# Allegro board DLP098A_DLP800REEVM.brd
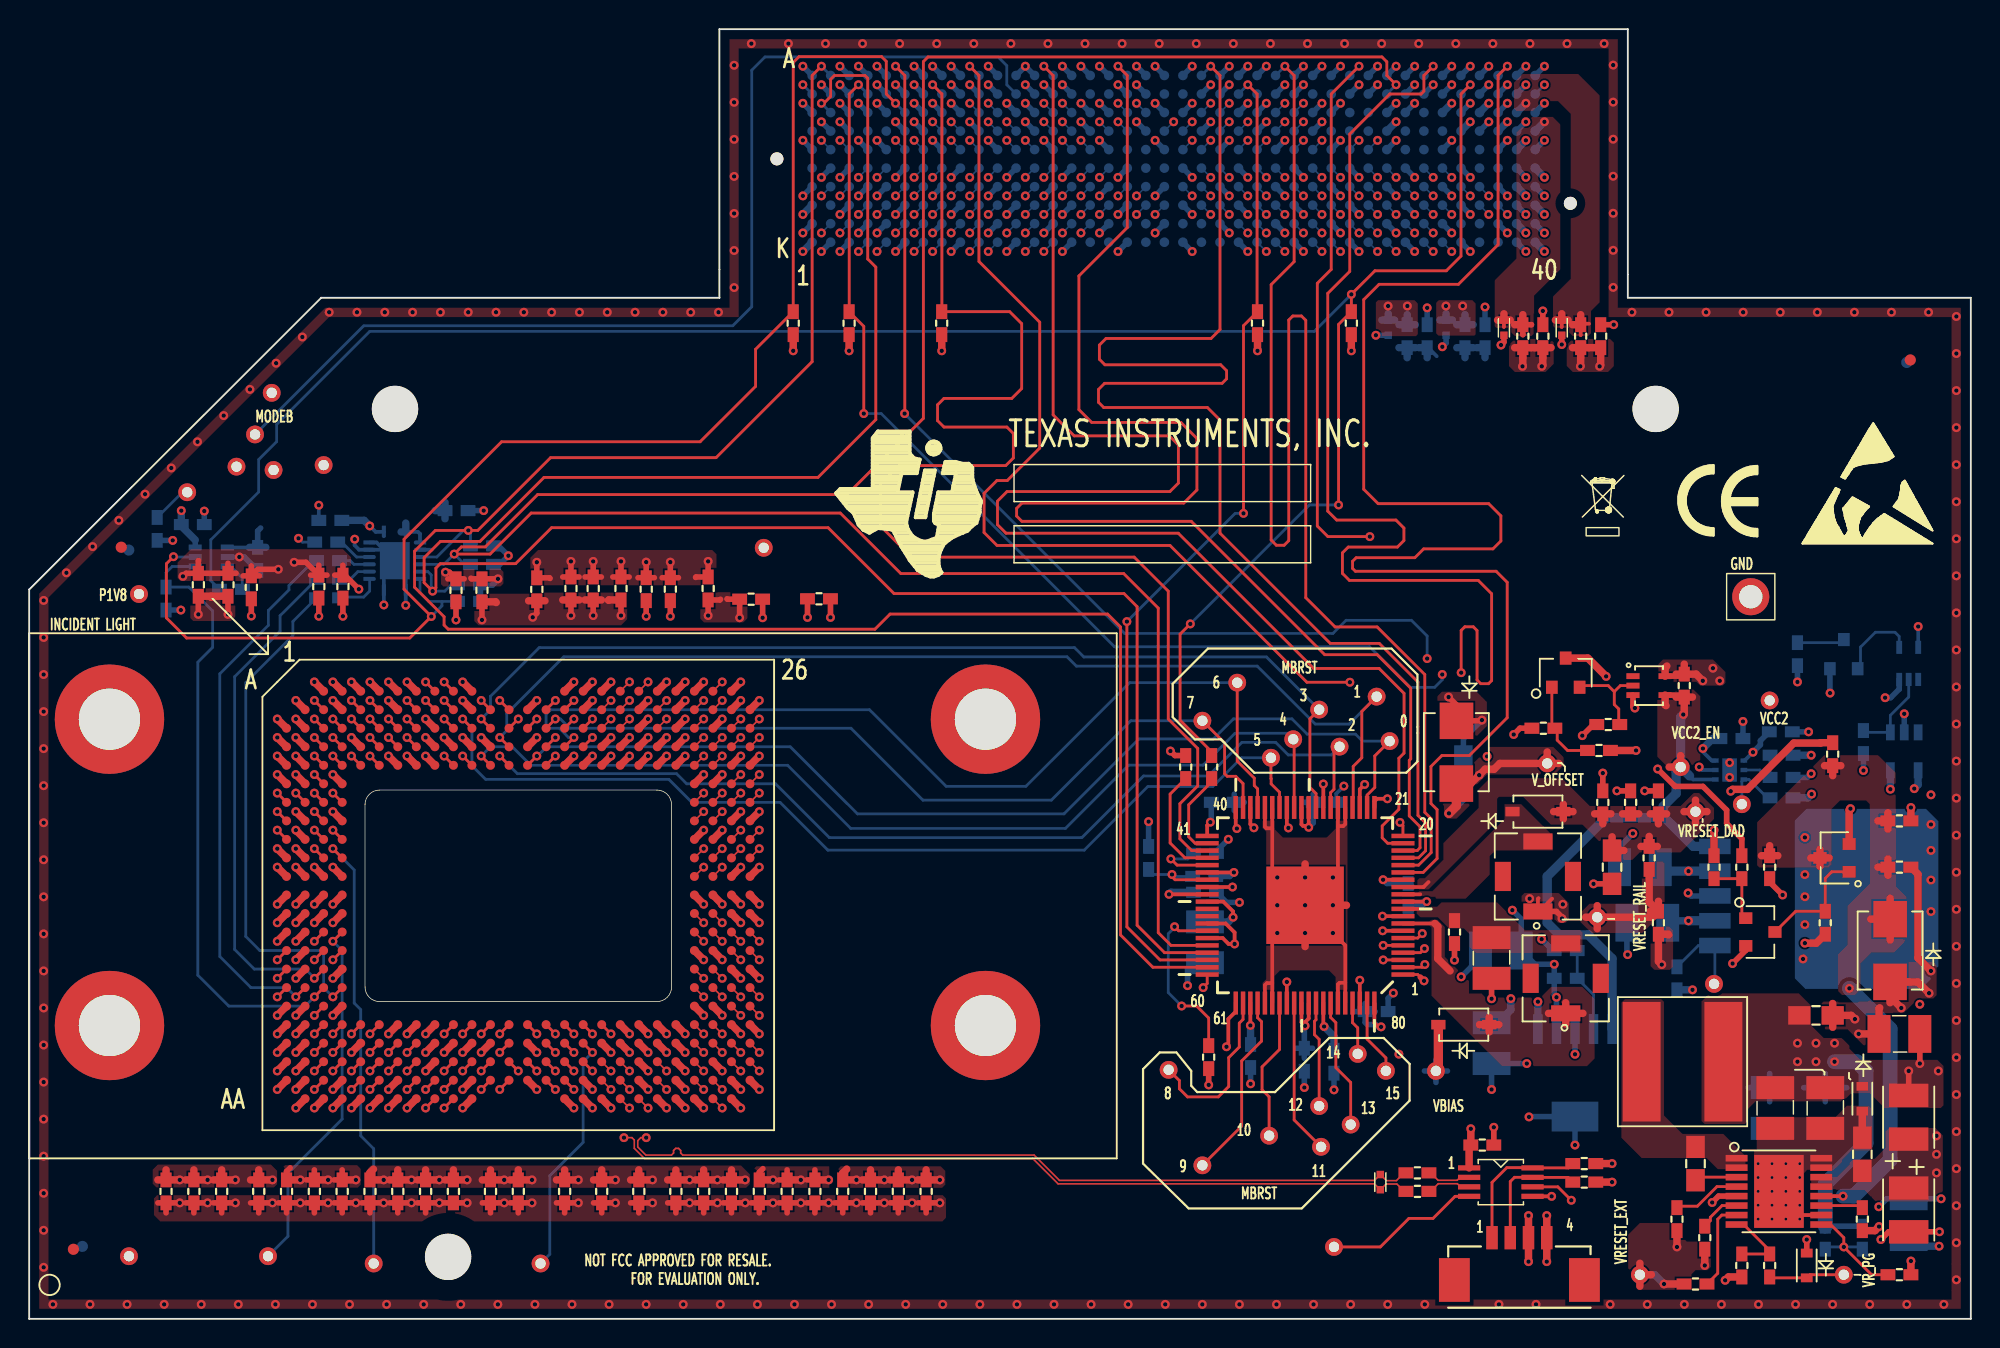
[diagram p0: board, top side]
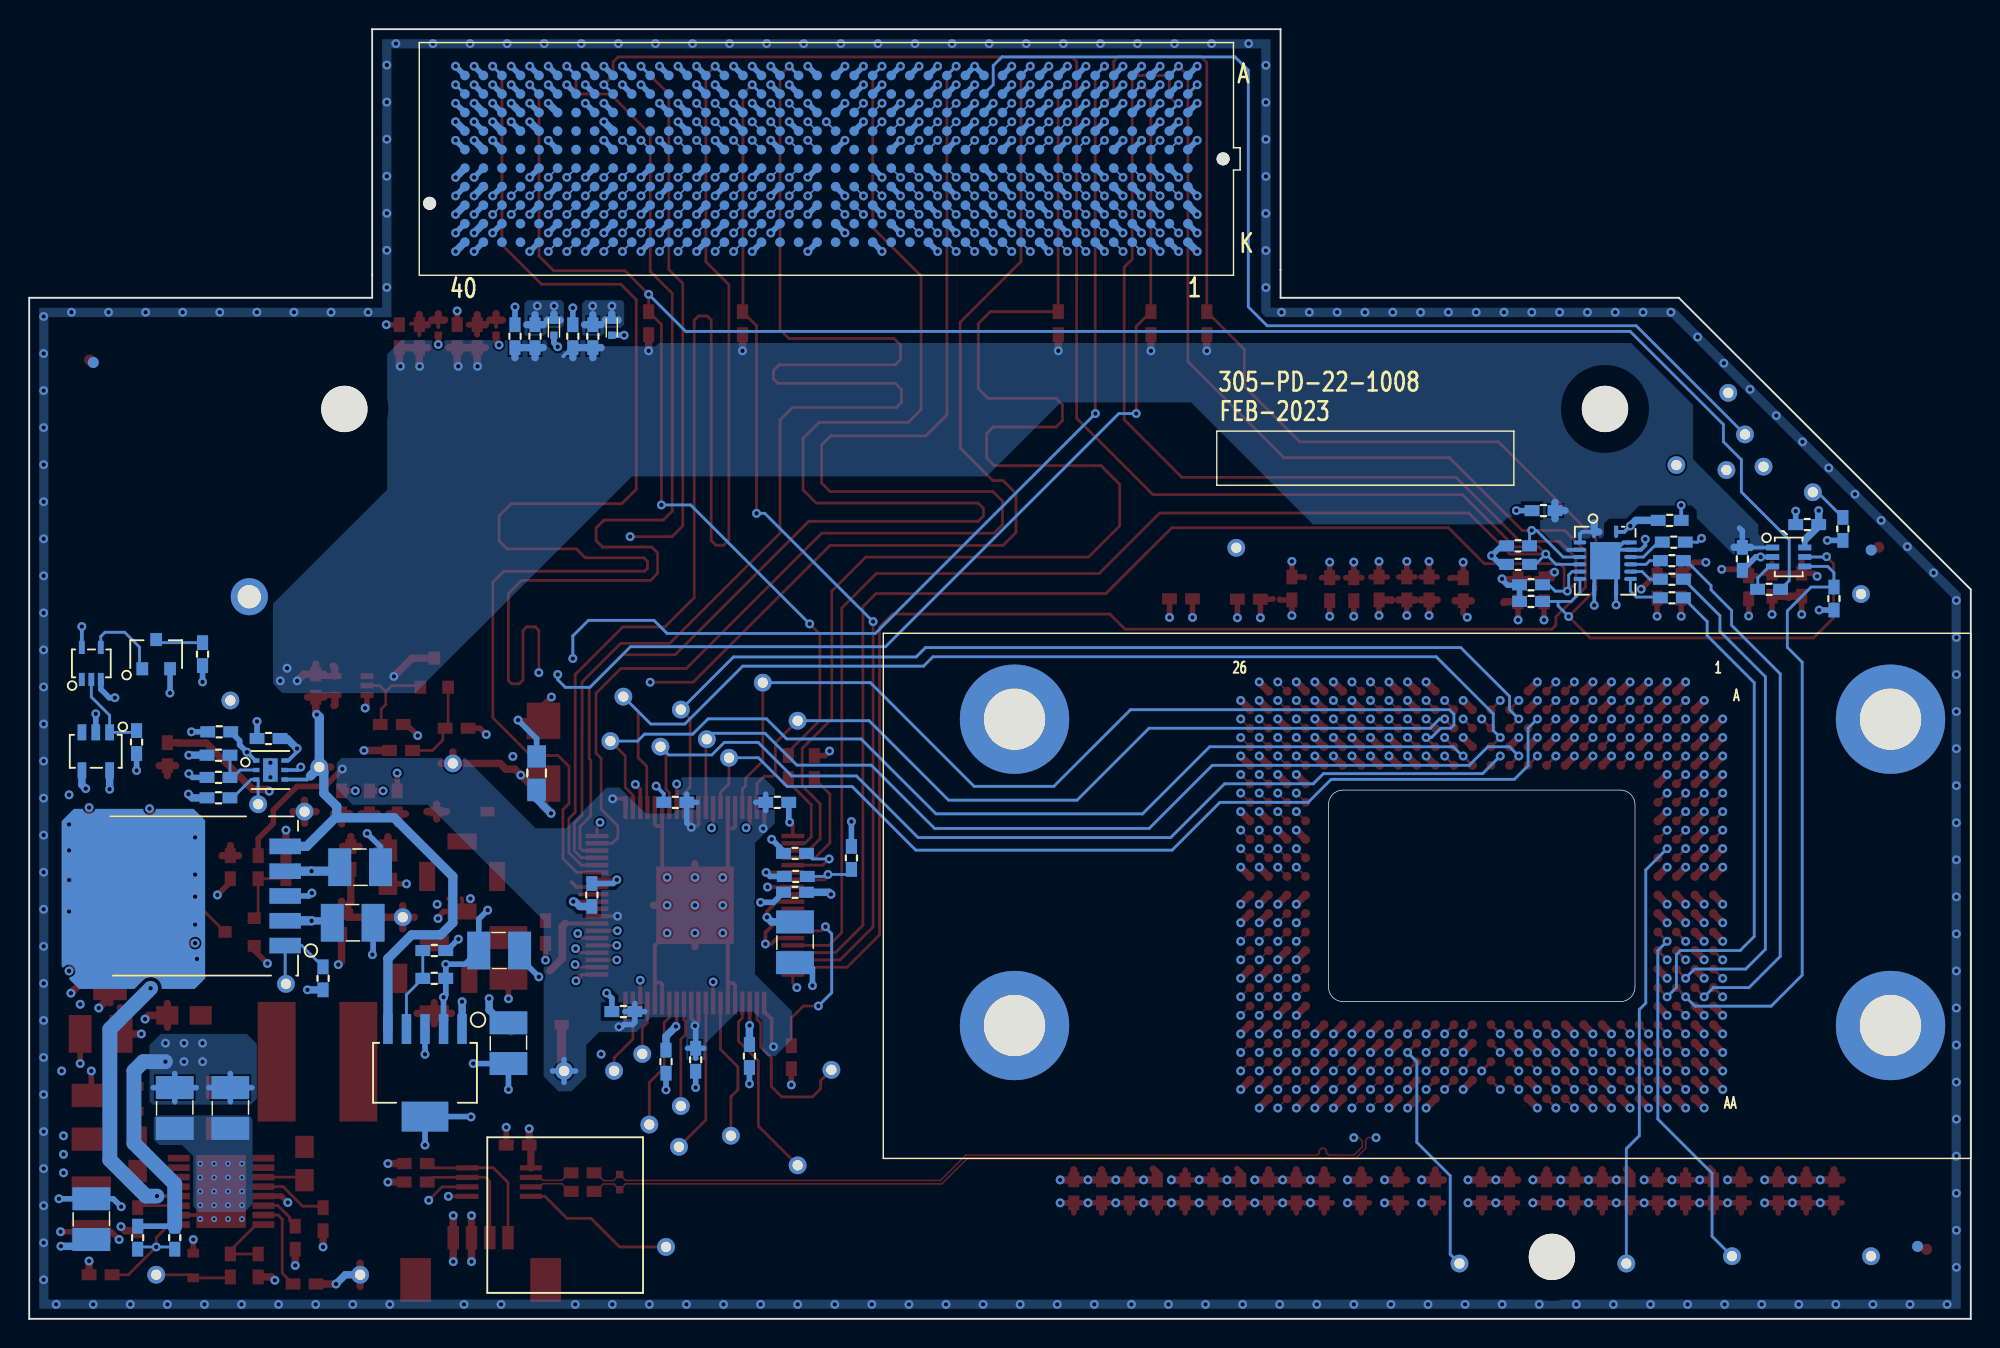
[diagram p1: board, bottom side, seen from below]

Outline 133.01 x 88.41 mm; copper layers: TOP, 02_GND1, 03_SIG1, 04_GND2, 05_SIG2, 06_PWR1, 07_PWR2, 08_SIG3, 09_GND3, 10_SIG4, 11_GND4, BOTTOM. Coordinates in mm from the lower left corner of the outline.
Outline path: 0,50 0,0 133.01,0 133.01,70 109.51,70 109.51,88.41 47.28,88.41 47.28,70 20,70 0,50 ; 23,35.25 23,22.75 arc(23.3,22.04) 24,21.75 43,21.75 arc(43.71,22.04) 44,22.75 44,35.25 arc(43.71,35.96) 43,36.25 24,36.25 arc(23.3,35.96) 23,35.25

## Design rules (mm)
net group DIFFPAIR36: nets DMD_TEMP_N DMD_TEMP_P
net group DIFFPAIR37: nets N16883881 N16883884
net group DIFF-A: nets S_DCLKA_N S_DCLKA_P S_DDA00_N S_DDA00_P S_DDA01_N S_DDA01_P S_DDA02_N S_DDA02_P S_DDA03_N S_DDA03_P S_DDA04_N S_DDA04_P S_DDA05_N S_DDA05_P S_DDA06_N S_DDA06_P S_DDA07_N S_DDA07_P S_DDA08_N S_DDA08_P S_DDA09_N S_DDA09_P S_DDA10_N S_DDA10_P S_DDA11_N S_DDA11_P S_DDA12_N S_DDA12_P S_DDA13_N S_DDA13_P S_DDA14_N S_DDA14_P S_DDA15_N S_DDA15_P S_SCTRLA_N S_SCTRLA_P
net group DIFF-B: nets S_DCLKB_N S_DCLKB_P S_DDB00_N S_DDB00_P S_DDB01_N S_DDB01_P S_DDB02_N S_DDB02_P S_DDB03_N S_DDB03_P S_DDB04_N S_DDB04_P S_DDB05_N S_DDB05_P S_DDB06_N S_DDB06_P S_DDB07_N S_DDB07_P S_DDB08_N S_DDB08_P S_DDB09_N S_DDB09_P S_DDB10_N S_DDB10_P S_DDB11_N S_DDB11_P S_DDB12_N S_DDB12_P S_DDB13_N S_DDB13_P S_DDB14_N S_DDB14_P S_DDB15_N S_DDB15_P S_SCTRLB_N S_SCTRLB_P
net group DIFF-C: nets M_DCLKA_N M_DCLKA_P M_DDA00_N M_DDA00_P M_DDA01_N M_DDA01_P M_DDA02_N M_DDA02_P M_DDA03_N M_DDA03_P M_DDA04_N M_DDA04_P M_DDA05_N M_DDA05_P M_DDA06_N M_DDA06_P M_DDA07_N M_DDA07_P M_DDA08_N M_DDA08_P M_DDA09_N M_DDA09_P M_DDA10_N M_DDA10_P M_DDA11_N M_DDA11_P M_DDA12_N M_DDA12_P M_DDA13_N M_DDA13_P M_DDA14_N M_DDA14_P M_DDA15_N M_DDA15_P M_SCTRLA_N M_SCTRLA_P
net group DIFF-D: nets M_DCLKB_N M_DCLKB_P M_DDB00_N M_DDB00_P M_DDB01_N M_DDB01_P M_DDB02_N M_DDB02_P M_DDB03_N M_DDB03_P M_DDB04_N M_DDB04_P M_DDB05_N M_DDB05_P M_DDB06_N M_DDB06_P M_DDB07_N M_DDB07_P M_DDB08_N M_DDB08_P M_DDB09_N M_DDB09_P M_DDB10_N M_DDB10_P M_DDB11_N M_DDB11_P M_DDB12_N M_DDB12_P M_DDB13_N M_DDB13_P M_DDB14_N M_DDB14_P M_DDB15_N M_DDB15_P M_SCTRLB_N M_SCTRLB_P
net group MBRST: nets MBRST0 MBRST1 MBRST2 MBRST3 MBRST4 MBRST5 MBRST6 MBRST7 MBRST8 MBRST9 MBRST10 MBRST11 MBRST12 MBRST13 MBRST14 MBRST15
net group PLN: nets N16949505
net group PWR: nets 3P3VAUX P3P3V1 P3P3V2 P3P3V3 P3P3V4 VADJ VIO_B_M2C VREF_A_M2C VREF_B_M2C VRESET_EN
net group SCP: nets SCP_CLK SCP_DMD_CSZ SCP_MISO SCP_MOSI
nets with their own width: min track width 0.381; nets GND VBIAS VCC2
nets with their own width: min track width 0.508; nets P12V

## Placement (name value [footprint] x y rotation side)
ASY1  -  []  96.34 7.16 180 bottom
C1  0.1 uF  [0603]  107.66 67.37 270 top
C2  1000 pF  [0402]  104.99 67.95 90 top
C3  1000 pF  [0402]  97.06 67.95 90 bottom
C4  0.1 uF  [0603]  99.73 67.37 270 bottom
C5  0.1 uF  [0603]  95.77 67.37 270 bottom
C6  1000 pF  [0402]  93.1 67.95 90 bottom
C7  1000 pF  [0402]  101.03 67.95 90 top
C8  0.1 uF  [0603]  103.69 67.37 270 top
C9  1 uF  [0603]  116.61 39.78 180 bottom
C10  10 uF  [1210]  110.34 30.96 0 bottom
C11  2.2 uF  [0603]  119.99 40.24 180 bottom
C12  10 uF  [1210]  110.85 27.15 0 bottom
C13  0.1 uF  [0603]  83.67 18.02 90 bottom
C14  0.1 uF  [0603]  89.38 17.63 90 bottom
C15  0.1 uF  [0603]  80.55 29.24 180 bottom
C16  4.7 uF  [0805]  98.25 37.41 270 bottom
C17  0.1 uF  [0603]  94.46 29.06 270 bottom
C18  10 uF  [1210]  80.55 25.81 90 bottom
C19  1 uF  [0603]  80.49 30.33 180 bottom
C20  0.1 uF  [0603]  76.68 31.6 270 bottom
C21  0.1 uF  [0603]  107.8 35.41 270 top
C22  0.1 uF  [0603]  109.7 35.41 270 top
C23  0.1 uF  [0603]  111.61 35.41 270 top
C24  4.7 uF  [0805]  108.43 30.96 90 top
C25  0.1 uF  [0603]  87.35 17.76 90 bottom
C26  0.1 uF  [0603]  92.31 21.06 180 bottom
C27  1 uF  [0603]  81.76 35.41 0 bottom
C28  1 uF  [0603]  88.75 35.41 180 bottom
C29  10 uF  [1210]  100.18 24.74 90 top
C30  0.1 uF  [0603]  97.64 26.52 90 top
C31  1 uF  [0603]  17.63 8.74 90 top
C32  1 uF  [0603]  19.53 8.74 90 top
C33  1 uF  [0603]  50.01 8.74 90 top
C34  1 uF  [0603]  53.82 8.74 90 top
C35  1 uF  [0603]  42.27 50.02 270 top
C36  1 uF  [0603]  21.49 50.2 270 top
C37  0.1 uF  [0603]  15.22 50.15 270 top
C38  0.1 uF  [0603]  49.46 49.33 180 top
C39  0.1 uF  [0603]  29.24 49.94 270 top
C40  0.1 uF  [0603]  51.92 8.74 90 top
C41  0.1 uF  [0603]  21.44 8.74 90 top
C42  0.1 uF  [0603]  46.51 50.07 270 top
C43  1 uF  [0603]  13.18 8.74 90 top
C44  1 uF  [0603]  39.22 8.74 90 top
C45  1 uF  [0603]  36.68 8.74 90 top
C46  1 uF  [0603]  13.62 50.32 270 top
C47  1 uF  [0603]  43.92 50.02 270 top
C48  1 uF  [0603]  38.64 50.07 270 top
C49  1 uF  [0603]  54.1 49.36 180 top
C50  1 uF  [0603]  40.54 50.07 270 top
C51  1 uF  [0603]  19.84 50.2 270 top
C52  1 uF  [0603]  11.59 50.32 270 top
C53  1 uF  [0603]  25.25 8.74 90 top
C54  1 uF  [0603]  27.15 8.74 90 top
C55  1 uF  [0603]  9.37 8.74 90 top
C56  1 uF  [0603]  41.76 8.74 90 top
C57  1 uF  [0603]  31.02 49.94 270 top
C58  0.1 uF  [0603]  37.11 50.07 270 top
C59  0.1 uF  [0603]  23.34 8.74 90 top
C60  0.1 uF  [0603]  15.72 8.74 90 top
C61  0.1 uF  [0603]  48.11 8.74 90 top
C62  0.1 uF  [0603]  44.3 8.74 90 top
C63  0.1 uF  [0603]  46.2 8.74 90 top
C64  0.1 uF  [0603]  31.6 8.74 90 top
C65  0.1 uF  [0603]  34.77 50.01 270 top
C66  0.1 uF  [0603]  55.73 8.74 90 top
C67  0.1 uF  [0603]  57.63 8.74 90 top
C68  0.1 uF  [0603]  59.54 8.74 90 top
C69  0.1 uF  [0603]  61.44 8.74 90 top
C70  0.1 uF  [0603]  33.5 8.74 90 top
C71  0.1 uF  [0603]  29.06 8.74 90 top
C72  0.1 uF  [0603]  11.28 8.74 90 top
C73  0.1 uF  [0603]  20.63 54.74 0 bottom
C74  0.1 uF  [0603]  29.27 55.41 180 bottom
C75  0.1 uF  [0603]  15.65 52.1 90 bottom
C76  0.1 uF  [0603]  11.21 54.45 180 bottom
C77  0.1 uF  [0603]  99.54 11.91 180 top
C78  180 pF  [0402]  92.56 9.37 90 top
C79  0.47 uF  [0805]  114.15 10.64 270 top
C80  10 uF  [1210]  123.04 14.45 90 top
C81  10 uF  [1210]  119.61 14.45 90 top
C82  10 uF  [1210]  119.23 14.45 90 bottom
C83  10 uF  [1210]  123.04 14.45 90 bottom
C84  10 uF  [1210]  128.12 19.53 0 top
C85  10 uF  [1210]  128.75 6.83 90 bottom
C86  22 uF  [1411]  128.75 7.47 270 top
C87  22 uF  [1411]  128.75 13.82 90 top
C88  4.7 uF  [0805]  125.58 11.28 270 top
C89  180 pF  [0603]  123.04 5.56 90 bottom
C90  2.2 uF  [0603]  112.88 6.83 90 top
C91  0.01 uF  [0603]  125.58 6.83 90 top
C92  4.7 uF  [0805]  122.4 20.8 180 top
C93  10 uF  [1210]  100.18 18.9 90 bottom
C94  10 uF  [1210]  100.81 25.25 0 bottom
D1  3SMBJ5926B-TP  [DO-214AA]  97.77 38.84 270 top
D2  STPS0560Z  [SOD-123]  103.35 34.77 180 top
D3  STPS0560Z  [SOD-123]  98.27 20.17 180 top
D5  RB501SM-30FHT2R  [SC-79]  121.77 3.66 270 top
D6  RB501SM-30FHT2R  [SC-79]  125.58 15.09 90 top
D7  3SMBJ5926B-TP  [DO-214AA]  127.48 25.25 90 top
J3  0532610471  [CONN4-53261-A_MOLEX]  102.08 5.56 0 top
J500  FMC 400POS CONN MALE  [CONN400-SEAM-40-A-A_SAM-ALPHA]  78.4 79.52 0 bottom
L1  68ohm @ 100MHz  [0603]  106.28 67.37 90 top
L2  68ohm @ 100MHz  [0603]  98.36 67.37 90 bottom
L3  68ohm @ 100MHz  [0603]  94.4 67.37 90 bottom
L4  68ohm @ 100MHz  [0603]  102.32 67.37 90 top
L5  22 uH  [BOURNS_WW_22UH]  103.35 30.33 180 top
L6  22 uH  [BOURNS_WW_22UH]  105.26 23.34 180 top
L7  47 uH  [SRN8040-470M]  113.26 17.63 0 top
NOREF  -  []  153.16 -43.22 0 top
NOREF#2  -  [unnamed#2]  111.42 62.38 0 top
NOREF#3  -  []  133.01 70 0 top
NOREF#4  -  [unnamed#3]  5.5 41.11 0 top
NOREF#5  -  [unnamed#2]  28.7 4.25 0 top
NOREF#6  -  [unnamed#3]  6.31 52.9 0 top
NOREF#7  -  []  23 22.75 0 top
NOREF#8  -  [unnamed#3]  65.51 20.11 0 top
NOREF#9  -  []  133.01 0 0 top
NOREF#10  -  []  94.69 58.03 0 top
NOREF#11  -  []  0 0 0 top
NOREF#12  -  []  0 50 0 top
NOREF#13  -  []  20 70 0 top
NOREF#14  -  []  79.25 47.54 0 top
NOREF#15  -  []  0 0 0 top
NOREF#16  -  []  47.28 88.41 0 top
NOREF#17  -  []  109.51 88.41 0 top
NOREF#18  -  []  41.77 45.36 0 top
NOREF#19  -  [unnamed#3]  65.51 41.11 0 top
NOREF#20  -  [unnamed#3]  128.86 65.74 0 top
NOREF#21  -  [unnamed#2]  25.06 62.38 0 top
NOREF#22  -  []  8.65 58.65 0 top
NOREF#23  -  [unnamed#3]  5.5 20.11 0 top
NOREF#24  -  []  24 21.75 90 top
NOREF#25  -  []  20 70 0 top
NOREF#26  -  []  109.51 88.41 0 top
NOREF#27  -  []  23.19 22.17 0 top
NOREF#28  -  [unnamed#3]  3.03 4.77 0 top
NOREF#29  -  [unnamed#3]  128.62 65.56 180 bottom
NOREF#30  -  [unnamed#3]  3.64 4.97 180 bottom
NOREF#31  -  [unnamed#3]  6.82 52.7 180 bottom
R1  2.2 K  [0603]  62.51 68.26 90 top
R2  2.2 K  [0603]  56.17 68.26 90 top
R3  2.2 K  [0603]  84.14 68.26 90 top
R4  2.2 K  [0603]  52.34 68.26 90 top
R5  2.2 K  [0603]  90.57 68.26 90 top
R6  0  [0603]  112.88 23.34 270 bottom
R7  115 K  [0603]  120.04 35.72 180 bottom
R8  115 K  [0603]  120.04 38.64 0 bottom
R9  16.2 K  [0603]  120.04 37.12 180 bottom
R10  10  [0603]  121.13 45.57 90 bottom
R11  2.2 K  [0603]  113.38 43.41 270 top
R12  33  [0603]  107.54 38.96 0 top
R13  100 K  [0603]  103.73 40.49 180 top
R14  100 K  [0603]  108.17 40.74 180 top
R15  2.2 K  [0603]  125.66 39.54 270 bottom
R16  33  [0603]  81 37.83 90 top
R17  0  [0603]  80.55 31.91 180 bottom
R18  0  [0603]  79.23 37.83 270 top
R19  0  [0603]  80.8 17.94 270 top
R20  0  [0603]  111.61 27.15 90 top
R21  100 K  [0603]  8.77 54.15 90 bottom
R22  33  [0603]  20.35 53.25 0 bottom
R23  33  [0603]  20.48 51.97 0 bottom
R24  33  [0603]  20.48 50.7 0 bottom
R25  33  [0603]  20.47 49.43 0 bottom
R26  100 K  [0603]  31.02 52.99 180 bottom
R27  100 K  [0603]  31.02 51.72 180 bottom
R28  100 K  [0603]  30.13 50.32 180 bottom
R29  100 K  [0603]  30.13 49.18 180 bottom
R30  33  [0603]  13.82 50.01 180 bottom
R31  100 K  [0603]  9.37 49.38 90 bottom
R32  2.2 K  [0603]  106.53 10.64 180 top
R33  2.2 K  [0603]  106.53 9.37 180 top
R34  51  [0603]  95.1 10.01 0 top
R35  51  [0603]  95.1 8.74 0 top
R41  0  [0603]  110.97 31.6 270 top
R42  100 K  [0603]  117.32 3.66 270 top
R43  100 K  [0603]  119.23 3.66 270 top
R44  100 K  [0603]  125.58 5.56 270 bottom
R45  80.6 K  [0603]  114.15 2.39 0 top
R46  0  [0603]  114.78 5.56 90 top
R47  6.49 K  [0603]  128.12 3.02 180 top
R48  1.6 K  [0603]  128.12 30.96 0 top
R49  0  [0603]  117.32 30.96 90 top
R50  100 K  [0603]  123.04 27.15 270 top
R51  0  [0603]  115.42 30.96 90 top
R52  100 K  [0603]  119.23 30.96 270 top
R53  0  [0603]  128.12 34.14 180 top
R54  0  [0603]  123.55 38.71 270 top
R55  3.4 K  [0603]  105.26 23.34 180 bottom
R56  464  [0603]  105.26 25.25 0 bottom
TP1  Testpoint_via  [TP-48RD28]  15.47 60.63 0 top
TP2  Testpoint_via  [TP-48RD28]  117.32 35.28 0 top
TP3  Testpoint_via  [TP-48RD28]  115.42 22.96 0 top
TP4  Testpoint_via  [TP-48RD28]  119.23 42.39 0 top
TP5  Testpoint_via  [TP-48RD28]  7.52 49.69 0 top
TP6  Testpoint_via  [TP-48RD28]  113.13 37.83 0 top
TP7  Testpoint_via  [TP-48RD28]  92.94 17 0 top
TP8  Testpoint_via  [TP-48RD28]  91.01 18.16 0 top
TP9  Testpoint_via  [TP-48RD28]  90.53 13.32 0 top
TP10  Testpoint_via  [TP-48RD28]  88.37 14.59 0 top
TP11  Testpoint_via  [TP-48RD28]  88.5 11.79 0 top
TP12  GND Testpoint  [TP-5006-GND_KEY]  117.93 49.5 0 top
TP13  Testpoint_via  [TP-48RD28]  84.94 12.56 0 top
TP14  Testpoint_via  [TP-48RD28]  80.37 10.52 0 top
TP15  Testpoint_via  [TP-48RD28]  78.06 17.07 0 top
TP16  Testpoint_via  [TP-48RD28]  80.37 41 0 top
TP17  Testpoint_via  [TP-48RD28]  82.76 43.61 0 top
TP18  Testpoint_via  [TP-48RD28]  85.07 38.46 0 top
TP19  Testpoint_via  [TP-48RD28]  86.59 39.73 0 top
TP20  Testpoint_via  [TP-48RD28]  88.37 41.77 0 top
TP21  Testpoint_via  [TP-48RD28]  89.77 39.23 0 top
TP22  Testpoint_via  [TP-48RD28]  92.31 42.65 0 top
TP23  Testpoint_via  [TP-48RD28]  93.2 39.61 0 top
TP24  Testpoint_via  [TP-48RD28]  103.99 38.07 0 top
TP25  Testpoint_via  [TP-48RD28]  107.42 27.53 0 top
TP26  Testpoint_via  [TP-48RD28]  96.37 16.99 270 top
TP27  Testpoint_via  [TP-48RD28]  114.15 34.77 0 top
TP28  Testpoint_via  [TP-48RD28]  16.36 4.29 270 top
TP29  Testpoint_via  [TP-48RD28]  23.6 3.79 0 top
TP30  Testpoint_via  [TP-48RD28]  10.82 56.67 0 top
TP31  Testpoint_via  [TP-48RD28]  35.03 3.79 0 top
TP32  Testpoint_via  [TP-48RD28]  50.32 52.86 0 top
TP33  Testpoint_via  [TP-48RD28]  6.83 4.29 0 top
TP34  Testpoint_via  [TP-48RD28]  14.2 58.42 0 top
TP35  Testpoint_via  [TP-48RD28]  16.74 58.19 0 top
TP36  Testpoint_via  [TP-48RD28]  16.61 63.48 0 top
TP37  Testpoint_via  [TP-48RD28]  20.17 58.53 0 top
TP38  Testpoint_via  [TP-48RD28]  89.38 4.93 0 top
TP40  Testpoint_via  [TP-48RD28]  124.31 3.02 0 top
TP41  Testpoint_via  [TP-48RD28]  110.34 3.02 0 top
U1  TPS7A25  [6-WSON]  116.49 37.62 180 bottom
U2  LP38513S-1.8  [TO-263-6]  122.02 28.99 180 bottom
U3  N-FET  [SOT-23-3]  105.26 44.3 0 top
U4  SN74AUP1G07DCK  [5-TSSOP]  110.97 43.41 0 top
U5  TPS3847085  [SOT-23-5]  128.45 38.91 270 bottom
U6  N-FET  [SOT-23-3]  124.31 45.57 180 bottom
U7  DLPA300  [ETQFP80]  87.4 28.35 90 top
U8  DLP780NE_DLP800RE_DLP780TE  [S600]  33.5 29.06 0 top
U9  SN74AVCH4T245RGYR  [VQFN]  25.05 51.97 180 bottom
U10  SN74LVC1T45  [6-TSSOP]  12.47 52.23 180 bottom
U11  TMP411A  [SOIC8-DGK_TI]  100.81 9.37 270 top
U13  LM43601  [16HTSSOP]  119.86 8.74 0 top
U14  SN74LVC1G04  [U_5_DCK]  128.75 44.93 90 bottom
U15  BSS84-7-F  [TO-236-3]  123.67 31.6 90 top
U16  N-FET  [SOT-23-3]  118.59 26.52 270 top
U17  TPS73801  [SOT-223-6]  105.89 16.87 0 bottom

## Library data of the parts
C1-C9 C11 C13-C17 C19-C28 C30-C79 C88-C92 = C
C10 C12 C18 C29 C80-C85 C93 C94 = C: Tolerance: TOL
C86 C87 = CAPACITOR_POL
D1 D7 = DIODE_SCHOTTKY_dsize
D2 D3 D5 D6 = SCHOTTKY DIODE
J3 = Conn_4
J500 = FMC 400POS CONNECTOR
L1-L4 L7 = L
L5 L6 = L_0
R1-R35 R41-R56 = R
TP1-TP38 TP40 TP41 = Testpoint
U1 = TPS7A25
U2 = LP38513S-1.8
U3 U6 U16 = N-FET
U4 = LOG,BUF,OPENDRN,SN74AUP1G07DCK
U5 = TPS3847085
U7 = DLPA300_0
U8 = DLP80RE_DLP78NE
U9 = SN74AVCH4T245RGYR_0
U10 = SN74LVC1T45
U11 = TMP411
U13 = LM43601
U14 = SN74LVC1G04
U15 = P-FET
U17 = TPS73801_0

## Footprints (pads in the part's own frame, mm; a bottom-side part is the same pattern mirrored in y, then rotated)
5-TSSOP
  rect 0.9x0.4 smd: 1(-1.1,0.65) 2(-1.1,0) 3(-1.1,-0.65) 4(1.1,-0.65) 5(1.1,0.65)
6-TSSOP
  rect 0.9x0.4 smd: 1(-1.1,0.65) 2(-1.1,0) 3(-1.1,-0.65) 4(1.1,-0.65) 5(1.1,0) 6(1.1,0.65)
6-WSON
  rect 0.45x0.3 smd: 1(-0.975,0.65) 2(-0.975,0) 3(-0.975,-0.65) 4(0.975,-0.65) 5(0.975,0) 6(0.975,0.65)
  rect 1x1.6 smd: 7(0,0)
16HTSSOP
  rect 1.5x0.45 smd: 1(-2.9,2.275) 2(-2.9,1.625) 3(-2.9,0.975) 4(-2.9,0.325) 5(-2.9,-0.325) 6(-2.9,-0.975) 7(-2.9,-1.625) 8(-2.9,-2.275) 9(2.9,-2.275) 10(2.9,-1.625) 11(2.9,-0.975) 12(2.9,-0.325) 13(2.9,0.325) 14(2.9,0.975) 15(2.9,1.625) 16(2.9,2.275)
  rect 3.4x5 smd: 17(0,0)
0402
  rect 0.508x0.508 smd: 1(-0.521,0) 2(0.521,0)
0603
  rect 1.016x0.762 smd: 1(-0.787,0) 2(0.787,0)
0805
  rect 1.524x1.27 smd: 1(-1.143,0) 2(1.143,0)
1210
  rect 1.575x2.591 smd: 1(-1.397,0) 2(1.397,0)
1411
  rect 1.6x2.7 smd: 1(-1.5,0) 2(1.5,0)
BOURNS_WW_22UH
  rect 2x1.1 smd: 1(0,2.4) 2(0,-2.4)
  rect 1.1x2 smd: 3(-2.4,0) 4(2.4,0)
CONN4-53261-A_MOLEX
  rect 2.108x2.997 smd: (-4.455,-2.9) (4.455,-2.9)
  rect 0.787x1.6 smd: 1(-1.875,0) 2(-0.625,0) 3(0.625,0) 4(1.875,0)
CONN400-SEAM-40-A-A_SAM-ALPHA
  round 0.889 hole 1.27 unplated: (-27.178,0) (27.178,3.048)
  round 0.66 smd: A01(-24.765,-5.715) A02(-23.495,-5.715) A03(-22.225,-5.715) A04(-20.955,-5.715) A05(-19.685,-5.715) A06(-18.415,-5.715) A07(-17.145,-5.715) A08(-15.875,-5.715) A09(-14.605,-5.715) A10(-13.335,-5.715) A11(-12.065,-5.715) A12(-10.795,-5.715) A13(-9.525,-5.715) A14(-8.255,-5.715) A15(-6.985,-5.715) A16(-5.715,-5.715) A17(-4.445,-5.715) A18(-3.175,-5.715) A19(-1.905,-5.715) A20(-0.635,-5.715) A21(0.635,-5.715) A22(1.905,-5.715) A23(3.175,-5.715) A24(4.445,-5.715) A25(5.715,-5.715) A26(6.985,-5.715) A27(8.255,-5.715) A28(9.525,-5.715) A29(10.795,-5.715) A30(12.065,-5.715) A31(13.335,-5.715) A32(14.605,-5.715) A33(15.875,-5.715) A34(17.145,-5.715) A35(18.415,-5.715) A36(19.685,-5.715) A37(20.955,-5.715) A38(22.225,-5.715) A39(23.495,-5.715) A40(24.765,-5.715) B01(-24.765,-4.445) B02(-23.495,-4.445) B03(-22.225,-4.445) B04(-20.955,-4.445) B05(-19.685,-4.445) B06(-18.415,-4.445) B07(-17.145,-4.445) B08(-15.875,-4.445) B09(-14.605,-4.445) B10(-13.335,-4.445) B11(-12.065,-4.445) B12(-10.795,-4.445) B13(-9.525,-4.445) B14(-8.255,-4.445) B15(-6.985,-4.445) B16(-5.715,-4.445) B17(-4.445,-4.445) B18(-3.175,-4.445) B19(-1.905,-4.445) B20(-0.635,-4.445) B21(0.635,-4.445) B22(1.905,-4.445) B23(3.175,-4.445) B24(4.445,-4.445) B25(5.715,-4.445) B26(6.985,-4.445) B27(8.255,-4.445) B28(9.525,-4.445) B29(10.795,-4.445) B30(12.065,-4.445) B31(13.335,-4.445) B32(14.605,-4.445) B33(15.875,-4.445) B34(17.145,-4.445) B35(18.415,-4.445) B36(19.685,-4.445) B37(20.955,-4.445) B38(22.225,-4.445) B39(23.495,-4.445) B40(24.765,-4.445) C01(-24.765,-3.175) C02(-23.495,-3.175) C03(-22.225,-3.175) C04(-20.955,-3.175) C05(-19.685,-3.175) C06(-18.415,-3.175) C07(-17.145,-3.175) C08(-15.875,-3.175) C09(-14.605,-3.175) C10(-13.335,-3.175) C11(-12.065,-3.175) C12(-10.795,-3.175) C13(-9.525,-3.175) C14(-8.255,-3.175) C15(-6.985,-3.175) C16(-5.715,-3.175) C17(-4.445,-3.175) C18(-3.175,-3.175) C19(-1.905,-3.175) C20(-0.635,-3.175) C21(0.635,-3.175) C22(1.905,-3.175) C23(3.175,-3.175) C24(4.445,-3.175) C25(5.715,-3.175) C26(6.985,-3.175) C27(8.255,-3.175) C28(9.525,-3.175) C29(10.795,-3.175) C30(12.065,-3.175) C31(13.335,-3.175) C32(14.605,-3.175) C33(15.875,-3.175) C34(17.145,-3.175) C35(18.415,-3.175) C36(19.685,-3.175) C37(20.955,-3.175) C38(22.225,-3.175) C39(23.495,-3.175) C40(24.765,-3.175) D01(-24.765,-1.905) D02(-23.495,-1.905) D03(-22.225,-1.905) D04(-20.955,-1.905) D05(-19.685,-1.905) D06(-18.415,-1.905) D07(-17.145,-1.905) D08(-15.875,-1.905) D09(-14.605,-1.905) D10(-13.335,-1.905) D11(-12.065,-1.905) D12(-10.795,-1.905) D13(-9.525,-1.905) D14(-8.255,-1.905) D15(-6.985,-1.905) D16(-5.715,-1.905) D17(-4.445,-1.905) D18(-3.175,-1.905) D19(-1.905,-1.905) D20(-0.635,-1.905) D21(0.635,-1.905) D22(1.905,-1.905) D23(3.175,-1.905) D24(4.445,-1.905) D25(5.715,-1.905) D26(6.985,-1.905) D27(8.255,-1.905) D28(9.525,-1.905) D29(10.795,-1.905) D30(12.065,-1.905) D31(13.335,-1.905) D32(14.605,-1.905) D33(15.875,-1.905) D34(17.145,-1.905) D35(18.415,-1.905) D36(19.685,-1.905) D37(20.955,-1.905) D38(22.225,-1.905) D39(23.495,-1.905) D40(24.765,-1.905) E01(-24.765,-0.635) E02(-23.495,-0.635) E03(-22.225,-0.635) E04(-20.955,-0.635) E05(-19.685,-0.635) E06(-18.415,-0.635) E07(-17.145,-0.635) E08(-15.875,-0.635) E09(-14.605,-0.635) E10(-13.335,-0.635) E11(-12.065,-0.635) E12(-10.795,-0.635) E13(-9.525,-0.635) E14(-8.255,-0.635) E15(-6.985,-0.635) E16(-5.715,-0.635) E17(-4.445,-0.635) E18(-3.175,-0.635) E19(-1.905,-0.635) E20(-0.635,-0.635) E21(0.635,-0.635) E22(1.905,-0.635) E23(3.175,-0.635) E24(4.445,-0.635) E25(5.715,-0.635) E26(6.985,-0.635) E27(8.255,-0.635) E28(9.525,-0.635) E29(10.795,-0.635) E30(12.065,-0.635) E31(13.335,-0.635) E32(14.605,-0.635) E33(15.875,-0.635) E34(17.145,-0.635) E35(18.415,-0.635) E36(19.685,-0.635) E37(20.955,-0.635) E38(22.225,-0.635) E39(23.495,-0.635) E40(24.765,-0.635) F01(-24.765,0.635) F02(-23.495,0.635) F03(-22.225,0.635) F04(-20.955,0.635) F05(-19.685,0.635) F06(-18.415,0.635) F07(-17.145,0.635) F08(-15.875,0.635) F09(-14.605,0.635) F10(-13.335,0.635) F11(-12.065,0.635) F12(-10.795,0.635) F13(-9.525,0.635) F14(-8.255,0.635) F15(-6.985,0.635) F16(-5.715,0.635) F17(-4.445,0.635) F18(-3.175,0.635) F19(-1.905,0.635) F20(-0.635,0.635) F21(0.635,0.635) F22(1.905,0.635) F23(3.175,0.635) F24(4.445,0.635) F25(5.715,0.635) F26(6.985,0.635) F27(8.255,0.635) F28(9.525,0.635) F29(10.795,0.635) F30(12.065,0.635) F31(13.335,0.635) F32(14.605,0.635) F33(15.875,0.635) F34(17.145,0.635) F35(18.415,0.635) F36(19.685,0.635) F37(20.955,0.635) F38(22.225,0.635) F39(23.495,0.635) F40(24.765,0.635) G01(-24.765,1.905) G02(-23.495,1.905) G03(-22.225,1.905) G04(-20.955,1.905) G05(-19.685,1.905) G06(-18.415,1.905) G07(-17.145,1.905) G08(-15.875,1.905) G09(-14.605,1.905) G10(-13.335,1.905) G11(-12.065,1.905) G12(-10.795,1.905) G13(-9.525,1.905) G14(-8.255,1.905) G15(-6.985,1.905) G16(-5.715,1.905) G17(-4.445,1.905) G18(-3.175,1.905) G19(-1.905,1.905) G20(-0.635,1.905) G21(0.635,1.905) G22(1.905,1.905) G23(3.175,1.905) G24(4.445,1.905) G25(5.715,1.905) G26(6.985,1.905) G27(8.255,1.905) G28(9.525,1.905) G29(10.795,1.905) G30(12.065,1.905) G31(13.335,1.905) G32(14.605,1.905) G33(15.875,1.905) G34(17.145,1.905) G35(18.415,1.905) G36(19.685,1.905) G37(20.955,1.905) G38(22.225,1.905) G39(23.495,1.905) G40(24.765,1.905) H01(-24.765,3.175) H02(-23.495,3.175) H03(-22.225,3.175) H04(-20.955,3.175) H05(-19.685,3.175) H06(-18.415,3.175) H07(-17.145,3.175) H08(-15.875,3.175) H09(-14.605,3.175) H10(-13.335,3.175) H11(-12.065,3.175) H12(-10.795,3.175) H13(-9.525,3.175) H14(-8.255,3.175) H15(-6.985,3.175) H16(-5.715,3.175) H17(-4.445,3.175) H18(-3.175,3.175) H19(-1.905,3.175) H20(-0.635,3.175) H21(0.635,3.175) H22(1.905,3.175) H23(3.175,3.175) H24(4.445,3.175) H25(5.715,3.175) H26(6.985,3.175) H27(8.255,3.175) H28(9.525,3.175) H29(10.795,3.175) H30(12.065,3.175) H31(13.335,3.175) H32(14.605,3.175) H33(15.875,3.175) H34(17.145,3.175) H35(18.415,3.175) H36(19.685,3.175) H37(20.955,3.175) H38(22.225,3.175) H39(23.495,3.175) H40(24.765,3.175) J01(-24.765,4.445) J02(-23.495,4.445) J03(-22.225,4.445) J04(-20.955,4.445) J05(-19.685,4.445) J06(-18.415,4.445) J07(-17.145,4.445) J08(-15.875,4.445) J09(-14.605,4.445) J10(-13.335,4.445) J11(-12.065,4.445) J12(-10.795,4.445) J13(-9.525,4.445) J14(-8.255,4.445) J15(-6.985,4.445) J16(-5.715,4.445) J17(-4.445,4.445) J18(-3.175,4.445) J19(-1.905,4.445) J20(-0.635,4.445) J21(0.635,4.445) J22(1.905,4.445) J23(3.175,4.445) J24(4.445,4.445) J25(5.715,4.445) J26(6.985,4.445) J27(8.255,4.445) J28(9.525,4.445) J29(10.795,4.445) J30(12.065,4.445) J31(13.335,4.445) J32(14.605,4.445) J33(15.875,4.445) J34(17.145,4.445) J35(18.415,4.445) J36(19.685,4.445) J37(20.955,4.445) J38(22.225,4.445) J39(23.495,4.445) J40(24.765,4.445) K01(-24.765,5.715) K02(-23.495,5.715) K03(-22.225,5.715) K04(-20.955,5.715) K05(-19.685,5.715) K06(-18.415,5.715) K07(-17.145,5.715) K08(-15.875,5.715) K09(-14.605,5.715) K10(-13.335,5.715) K11(-12.065,5.715) K12(-10.795,5.715) K13(-9.525,5.715) K14(-8.255,5.715) K15(-6.985,5.715) K16(-5.715,5.715) K17(-4.445,5.715) K18(-3.175,5.715) K19(-1.905,5.715) K20(-0.635,5.715) K21(0.635,5.715) K22(1.905,5.715) K23(3.175,5.715) K24(4.445,5.715) K25(5.715,5.715) K26(6.985,5.715) K27(8.255,5.715) K28(9.525,5.715) K29(10.795,5.715) K30(12.065,5.715) K31(13.335,5.715) K32(14.605,5.715) K33(15.875,5.715) K34(17.145,5.715) K35(18.415,5.715) K36(19.685,5.715) K37(20.955,5.715) K38(22.225,5.715) K39(23.495,5.715) K40(24.765,5.715)
DO-214AA
  rect 2.5x2.3 smd: 1(-2.15,0.009) 2(2.15,0)
ETQFP80
  rect 0.305x1.575 smd: 1(-4.75,-6.706) 2(-4.249,-6.706) 3(-3.749,-6.706) 4(-3.251,-6.706) 5(-2.751,-6.706) 6(-2.25,-6.706) 7(-1.75,-6.706) 8(-1.25,-6.706) 9(-0.749,-6.706) 10(-0.249,-6.706) 11(0.249,-6.706) 12(0.749,-6.706) 13(1.25,-6.706) 14(1.75,-6.706) 15(2.25,-6.706) 16(2.751,-6.706) 17(3.251,-6.706) 18(3.749,-6.706) 19(4.249,-6.706) 20(4.75,-6.706) 41(4.75,6.706) 42(4.249,6.706) 43(3.749,6.706) 44(3.251,6.706) 45(2.751,6.706) 46(2.25,6.706) 47(1.75,6.706) 48(1.25,6.706) 49(0.749,6.706) 50(0.249,6.706) 51(-0.249,6.706) 52(-0.749,6.706) 53(-1.25,6.706) 54(-1.75,6.706) 55(-2.25,6.706) 56(-2.751,6.706) 57(-3.251,6.706) 58(-3.749,6.706) 59(-4.249,6.706) 60(-4.75,6.706)
  rect 1.575x0.305 smd: 21(6.706,-4.75) 22(6.706,-4.249) 23(6.706,-3.749) 24(6.706,-3.251) 25(6.706,-2.751) 26(6.706,-2.25) 27(6.706,-1.75) 28(6.706,-1.25) 29(6.706,-0.749) 30(6.706,-0.249) 31(6.706,0.249) 32(6.706,0.749) 33(6.706,1.25) 34(6.706,1.75) 35(6.706,2.25) 36(6.706,2.751) 37(6.706,3.251) 38(6.706,3.749) 39(6.706,4.249) 40(6.706,4.75) 61(-6.706,4.75) 62(-6.706,4.249) 63(-6.706,3.749) 64(-6.706,3.251) 65(-6.706,2.751) 66(-6.706,2.25) 67(-6.706,1.75) 68(-6.706,1.25) 69(-6.706,0.749) 70(-6.706,0.249) 71(-6.706,-0.249) 72(-6.706,-0.749) 73(-6.706,-1.25) 74(-6.706,-1.75) 75(-6.706,-2.25) 76(-6.706,-2.751) 77(-6.706,-3.251) 78(-6.706,-3.749) 79(-6.706,-4.249) 80(-6.706,-4.75)
  rect 5.309x5.309 smd: 81(0,0)
S600
  round 0.61 smd: A3(-13.335,13.97) A4(-12.065,13.97) A5(-10.795,13.97) A6(-9.525,13.97) A7(-8.255,13.97) A8(-6.985,13.97) A9(-5.715,13.97) A10(-4.445,13.97) A11(-3.175,13.97) A16(3.175,13.97) A17(4.445,13.97) A18(5.715,13.97) A19(6.985,13.97) A20(8.255,13.97) A21(9.525,13.97) A22(10.795,13.97) A23(12.065,13.97) A24(13.335,13.97) A25(14.605,13.97) AA2(-14.605,-13.97) AA3(-13.335,-13.97) AA4(-12.065,-13.97) AA5(-10.795,-13.97) AA6(-9.525,-13.97) AA7(-8.255,-13.97) AA8(-6.985,-13.97) AA9(-5.715,-13.97) AA10(-4.445,-13.97) AA11(-3.175,-13.97) AA16(3.175,-13.97) AA17(4.445,-13.97) AA18(5.715,-13.97) AA19(6.985,-13.97) AA20(8.255,-13.97) AA21(9.525,-13.97) AA22(10.795,-13.97) AA23(12.065,-13.97) AA24(13.335,-13.97) AA25(14.605,-13.97) B2(-14.605,12.7) B3(-13.335,12.7) B4(-12.065,12.7) B5(-10.795,12.7) B6(-9.525,12.7) B7(-8.255,12.7) B8(-6.985,12.7) B9(-5.715,12.7) B10(-4.445,12.7) B11(-3.175,12.7) B12(-1.905,12.7) B13(-0.635,12.7) B14(0.635,12.7) B15(1.905,12.7) B16(3.175,12.7) B17(4.445,12.7) B18(5.715,12.7) B19(6.985,12.7) B20(8.255,12.7) B21(9.525,12.7) B22(10.795,12.7) B23(12.065,12.7) B24(13.335,12.7) B25(14.605,12.7) B26(15.875,12.7) C1(-15.875,11.43) C2(-14.605,11.43) C3(-13.335,11.43) C4(-12.065,11.43) C5(-10.795,11.43) C6(-9.525,11.43) C7(-8.255,11.43) C8(-6.985,11.43) C9(-5.715,11.43) C10(-4.445,11.43) C11(-3.175,11.43) C12(-1.905,11.43) C13(-0.635,11.43) C14(0.635,11.43) C15(1.905,11.43) C16(3.175,11.43) C17(4.445,11.43) C18(5.715,11.43) C19(6.985,11.43) C20(8.255,11.43) C21(9.525,11.43) C22(10.795,11.43) C23(12.065,11.43) C24(13.335,11.43) C25(14.605,11.43) C26(15.875,11.43) D1(-15.875,10.16) D2(-14.605,10.16) D3(-13.335,10.16) D4(-12.065,10.16) D5(-10.795,10.16) D6(-9.525,10.16) D7(-8.255,10.16) D8(-6.985,10.16) D9(-5.715,10.16) D10(-4.445,10.16) D11(-3.175,10.16) D12(-1.905,10.16) D13(-0.635,10.16) D14(0.635,10.16) D15(1.905,10.16) D16(3.175,10.16) D17(4.445,10.16) D18(5.715,10.16) D19(6.985,10.16) D20(8.255,10.16) D21(9.525,10.16) D22(10.795,10.16) D23(12.065,10.16) D24(13.335,10.16) D25(14.605,10.16) D26(15.875,10.16) E1(-15.875,8.89) E2(-14.605,8.89) E3(-13.335,8.89) E4(-12.065,8.89) E5(-10.795,8.89) E6(-9.525,8.89) E7(-8.255,8.89) E8(-6.985,8.89) E9(-5.715,8.89) E10(-4.445,8.89) E11(-3.175,8.89) E12(-1.905,8.89) E13(-0.635,8.89) E14(0.635,8.89) E15(1.905,8.89) E16(3.175,8.89) E17(4.445,8.89) E18(5.715,8.89) E19(6.985,8.89) E20(8.255,8.89) E21(9.525,8.89) E22(10.795,8.89) E23(12.065,8.89) E24(13.335,8.89) E25(14.605,8.89) E26(15.875,8.89) F1(-15.875,7.62) F2(-14.605,7.62) F3(-13.335,7.62) F4(-12.065,7.62) F23(12.065,7.62) F24(13.335,7.62) F25(14.605,7.62) F26(15.875,7.62) G1(-15.875,6.35) G2(-14.605,6.35) G3(-13.335,6.35) G4(-12.065,6.35) G23(12.065,6.35) G24(13.335,6.35) G25(14.605,6.35) G26(15.875,6.35) H1(-15.875,5.08) H2(-14.605,5.08) H3(-13.335,5.08) H4(-12.065,5.08) H23(12.065,5.08) H24(13.335,5.08) H25(14.605,5.08) H26(15.875,5.08) J1(-15.875,3.81) J2(-14.605,3.81) J3(-13.335,3.81) J4(-12.065,3.81) J23(12.065,3.81) J24(13.335,3.81) J25(14.605,3.81) J26(15.875,3.81) K1(-15.875,2.54) K2(-14.605,2.54) K3(-13.335,2.54) K4(-12.065,2.54) K23(12.065,2.54) K24(13.335,2.54) K25(14.605,2.54) K26(15.875,2.54) L1(-15.875,1.27) L2(-14.605,1.27) L3(-13.335,1.27) L4(-12.065,1.27) L23(12.065,1.27) L24(13.335,1.27) L25(14.605,1.27) L26(15.875,1.27) M1(-15.875,0) M2(-14.605,0) M3(-13.335,0) M4(-12.065,0) M23(12.065,0) M24(13.335,0) M25(14.605,0) M26(15.875,0) N1(-15.875,-1.27) N2(-14.605,-1.27) N3(-13.335,-1.27) N4(-12.065,-1.27) N23(12.065,-1.27) N24(13.335,-1.27) N25(14.605,-1.27) N26(15.875,-1.27) P1(-15.875,-2.54) P2(-14.605,-2.54) P3(-13.335,-2.54) P4(-12.065,-2.54) P23(12.065,-2.54) P24(13.335,-2.54) P25(14.605,-2.54) P26(15.875,-2.54) R1(-15.875,-3.81) R2(-14.605,-3.81) R3(-13.335,-3.81) R4(-12.065,-3.81) R23(12.065,-3.81) R24(13.335,-3.81) R25(14.605,-3.81) R26(15.875,-3.81) T1(-15.875,-5.08) T2(-14.605,-5.08) T3(-13.335,-5.08) T4(-12.065,-5.08) T23(12.065,-5.08) T24(13.335,-5.08) T25(14.605,-5.08) T26(15.875,-5.08) U1(-15.875,-6.35) U2(-14.605,-6.35) U3(-13.335,-6.35) U4(-12.065,-6.35) U23(12.065,-6.35) U24(13.335,-6.35) U25(14.605,-6.35) U26(15.875,-6.35) V1(-15.875,-7.62) V2(-14.605,-7.62) V3(-13.335,-7.62) V4(-12.065,-7.62) V23(12.065,-7.62) V24(13.335,-7.62) V25(14.605,-7.62) V26(15.875,-7.62) W1(-15.875,-8.89) W2(-14.605,-8.89) W3(-13.335,-8.89) W4(-12.065,-8.89) W5(-10.795,-8.89) W6(-9.525,-8.89) W7(-8.255,-8.89) W8(-6.985,-8.89) W9(-5.715,-8.89) W10(-4.445,-8.89) W11(-3.175,-8.89) W12(-1.905,-8.89) W13(-0.635,-8.89) W14(0.635,-8.89) W15(1.905,-8.89) W16(3.175,-8.89) W17(4.445,-8.89) W18(5.715,-8.89) W19(6.985,-8.89) W20(8.255,-8.89) W21(9.525,-8.89) W22(10.795,-8.89) W23(12.065,-8.89) W24(13.335,-8.89) W25(14.605,-8.89) W26(15.875,-8.89) X1(-15.875,-10.16) X2(-14.605,-10.16) X3(-13.335,-10.16) X4(-12.065,-10.16) X5(-10.795,-10.16) X6(-9.525,-10.16) X7(-8.255,-10.16) X8(-6.985,-10.16) X9(-5.715,-10.16) X10(-4.445,-10.16) X11(-3.175,-10.16) X12(-1.905,-10.16) X13(-0.635,-10.16) X14(0.635,-10.16) X15(1.905,-10.16) X16(3.175,-10.16) X17(4.445,-10.16) X18(5.715,-10.16) X19(6.985,-10.16) X20(8.255,-10.16) X21(9.525,-10.16) X22(10.795,-10.16) X23(12.065,-10.16) X24(13.335,-10.16) X25(14.605,-10.16) X26(15.875,-10.16) Y1(-15.875,-11.43) Y2(-14.605,-11.43) Y3(-13.335,-11.43) Y4(-12.065,-11.43) Y5(-10.795,-11.43) Y6(-9.525,-11.43) Y7(-8.255,-11.43) Y8(-6.985,-11.43) Y9(-5.715,-11.43) Y10(-4.445,-11.43) Y11(-3.175,-11.43) Y12(-1.905,-11.43) Y13(-0.635,-11.43) Y14(0.635,-11.43) Y15(1.905,-11.43) Y16(3.175,-11.43) Y17(4.445,-11.43) Y18(5.715,-11.43) Y19(6.985,-11.43) Y20(8.255,-11.43) Y21(9.525,-11.43) Y22(10.795,-11.43) Y23(12.065,-11.43) Y24(13.335,-11.43) Y25(14.605,-11.43) Y26(15.875,-11.43) Z1(-15.875,-12.7) Z2(-14.605,-12.7) Z3(-13.335,-12.7) Z4(-12.065,-12.7) Z5(-10.795,-12.7) Z6(-9.525,-12.7) Z7(-8.255,-12.7) Z8(-6.985,-12.7) Z9(-5.715,-12.7) Z10(-4.445,-12.7) Z11(-3.175,-12.7) Z12(-1.905,-12.7) Z13(-0.635,-12.7) Z14(0.635,-12.7) Z15(1.905,-12.7) Z16(3.175,-12.7) Z17(4.445,-12.7) Z18(5.715,-12.7) Z19(6.985,-12.7) Z20(8.255,-12.7) Z21(9.525,-12.7) Z22(10.795,-12.7) Z23(12.065,-12.7) Z24(13.335,-12.7) Z25(14.605,-12.7) Z26(15.875,-12.7)
SC-79
  rect 0.6x0.8 smd: A(-0.85,0) C(0.85,0)
SOD-123
  rect 0.97x0.65 smd: A(-1.74,0) C(1.74,0)
SOIC8-DGK_TI
  rect 0.356x1.524 smd: 1(-0.975,-2.173) 2(-0.325,-2.173) 3(0.325,-2.173) 4(0.975,-2.173) 5(0.975,2.173) 6(0.325,2.173) 7(-0.325,2.173) 8(-0.975,2.173)
SOT-23-3
  rect 0.8x0.9 smd: 1(-0.95,-1) 2(0.95,-1) 3(-0.003,1)
SOT-23-5
  rect 1.1x0.6 smd: 1(-1.3,0.95) 2(-1.3,0) 3(-1.3,-0.95) 4(1.3,-0.95) 5(1.3,0.95)
SOT-223-6
  rect 0.65x2.05 smd: 1(-2.54,-3) 2(-1.27,-3) 3(0,-3) 4(1.27,-3) 5(2.54,-3)
  rect 3.2x2.05 smd: 6(0,3)
SRN8040-470M
  rect 2.6x8.2 smd: 1(-2.8,0) 2(2.8,0)
TO-236-3
  rect 0.8x0.9 smd: 1(-0.95,-1) 2(0.95,-1) 3(0,1)
TO-263-6
  rect 2.16x1.07 smd: 1(6.545,-3.4) 2(6.545,-1.7) 3(6.545,0) 4(6.545,1.7) 5(6.545,3.4)
  custom 1.747x1.747 smd: 6(-4.13,0)
TP-48RD28
  round 1.219 hole 0.711: 1(0,0)
TP-5006-GND_KEY
  round 2.54 hole 1.6: 1(0,0)
U_5_DCK
  rect 0.9x0.4 smd: 1(-1.1,0.65) 2(-1.1,0) 3(-1.1,-0.65) 4(1.1,-0.65) 5(1.1,0.65)
unnamed#2
  round 5.08 hole 3.175 unplated: (0,0)
unnamed#3
  round 7.493 hole 4.201: 1(0,0)
VQFN
  custom 0.07x0.07 smd: 1(-0.75,1.975) 2(-1.725,1.25) 3(-1.725,0.75) 4(-1.725,0.25) 5(-1.725,-0.25) 6(-1.725,-0.75) 7(-1.725,-1.25) 8(-0.75,-1.975) 9(0.75,-1.975) 10(1.725,-1.25) 11(1.725,-0.75) 12(1.725,-0.25) 13(1.725,0.25) 14(1.725,0.75) 15(1.725,1.25) 16(0.75,1.975)
  rect 2.05x2.55 smd: 17(0,0)

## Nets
GND: C1.1 C2.1 C3.1 C4.1 C5.1 C6.1 C7.1 C8.1 C9.1 C10.1 C11.1 C12.1 C13.1 C14.1 C15.1 C16.1 C17.1 C18.1 C19.1 C20.1 C21.1 C22.1 C23.1 C24.1 C25.1 C26.1 C27.1 C28.1 C29.1 C30.1 C31.1 C32.1 C33.1 C34.1 C35.1 C36.1 C37.1 C38.1 C39.1 C40.1 C41.1 C42.1 C43.1 C44.1 C45.1 C46.1 C47.1 C48.1 C49.1 C50.1 C51.1 C52.1 C53.1 C54.1 C55.1 C56.1 C57.1 C58.1 C59.1 C60.1 C61.1 C62.1 C63.1 C64.1 C65.1 C66.1 C67.1 C68.1 C69.1 C70.1 C71.1 C72.1 C73.1 C74.1 C75.1 C76.1 C77.1 C80.2 C81.2 C82.2 C83.2 C84.2 C85.2 C86.2 C87.2 C89.2 C92.2 C93.1 C94.1 D1.1(ANODE) D5.A D6.C J3.4 J500.A01(GND#A01) J500.A03(DP1_M2C_N) J500.A04(GND#A04) J500.A05(GND#A05) J500.A07(DP2_M2C_N) J500.A08(GND#A08) J500.A09(GND#A09) J500.A11(DP3_M2C_N) J500.A12(GND#A12) J500.A13(GND#A13) J500.A15(DP4_M2C_N) J500.A16(GND#A16) J500.A17(GND#A17) J500.A19(DP5_M2C_N) J500.A20(GND#A20) J500.A21(GND#A21) J500.A23(DP1_C2M_N) J500.A24(GND#A24) J500.A25(GND#A25) J500.A27(DP2_C2M_N) J500.A28(GND#A28) J500.A29(GND#A29) J500.A31(DP3_C2M_N) J500.A32(GND#A32) J500.A33(GND#A33) J500.A35(DP4_C2M_N) J500.A36(GND#A36) J500.A37(GND#A37) J500.A39(DP5_C2M_N) J500.A40(GND#A40) J500.B02(GND#B02) J500.B03(GND#B03) J500.B05(DP9_M2C_N) J500.B06(GND#B06) J500.B07(GND#B07) J500.B09(DP8_M2C_N) J500.B10(GND#B10) J500.B11(GND#B11) J500.B13(DP7_M2C_N) J500.B14(GND#B14) J500.B15(GND#B15) J500.B18(GND#B18) J500.B19(GND#B19) J500.B22(GND#B22) J500.B23(GND#B23) J500.B26(GND#B26) J500.B27(GND#B27) J500.B30(GND#B30) J500.B31(GND#B31) J500.B33(DP7_C2M_N) J500.B34(GND#B34) J500.B35(GND#B35) J500.B37(DP6_C2M_N) J500.B38(GND#B38) J500.B39(GND#B39) J500.C01(GND#C01) J500.C03(DP0_C2M_N) J500.C04(GND#C04) J500.C05(GND#C05) J500.C07(DP0_M2C_N) J500.C08(GND#C08) J500.C09(GND#C09) J500.C12(GND#C12) J500.C13(GND#C13) J500.C16(GND#C16) J500.C17(GND#C17) J500.C20(GND#C20) J500.C21(GND#C21) J500.C24(GND#C24) J500.C25(GND#C25) J500.C28(GND#C28) J500.C29(GND#C29) J500.C32(GND#C32) J500.C33(GND#C33) J500.C36(GND#C36) J500.C38(GND#C38) J500.C40(GND#C40) J500.D02(GND#D02) J500.D03(GND#D03) J500.D06(GND#D06) J500.D07(GND#D07) J500.D10(GND#D10) J500.D13(GND#D13) J500.D16(GND#D16) J500.D19(GND#D19) J500.D22(GND#D22) J500.D25(GND#D25) J500.D28(GND#D28) J500.D37(GND#D37) J500.D39(GND#D39) J500.E01(GND#E01) J500.E04(GND#E04) J500.E05(GND#E05) J500.E08(GND#E08) J500.E11(GND#E11) J500.E14(GND#E14) J500.E17(GND#E17) J500.E20(GND#E20) J500.E23(GND#E23) J500.E26(GND#E26) J500.E29(GND#E29) J500.E32(GND#E32) J500.E35(GND#E35) J500.E38(GND#E38) J500.E40(GND#E40) J500.F02(GND#F02) J500.F03(GND#F03) J500.F06(GND#F06) J500.F09(GND#F09) J500.F12(GND#F12) J500.F15(GND#F15) J500.F18(GND#F18) J500.F21(GND#F21) J500.F24(GND#F24) J500.F27(GND#F27) J500.F30(GND#F30) J500.F33(GND#F33) J500.F36(GND#F36) J500.F39(GND#F39) J500.G01(GND#G01) J500.G04(GND#G04) J500.G05(GND#G05) J500.G08(GND#G08) J500.G11(GND#G11) J500.G14(GND#G14) J500.G17(GND#G17) J500.G20(GND#G20) J500.G23(GND#G23) J500.G26(GND#G26) J500.G29(GND#G29) J500.G32(GND#G32) J500.G35(GND#G35) J500.G38(GND#G38) J500.G40(GND#G40) J500.H03(GND#H03) J500.H06(GND#H06) J500.H09(GND#H09) J500.H12(GND#H12) J500.H15(GND#H15) J500.H18(GND#H18) J500.H21(GND#H21) J500.H24(GND#H24) J500.H27(GND#H27) J500.H30(GND#H30) J500.H33(GND#H33) J500.H36(GND#H36) J500.H39(GND#H39) J500.J01(GND#J01) J500.J04(GND#J04) J500.J05(GND#J05) J500.J08(GND#J08) J500.J11(GND#J11) J500.J14(GND#J14) J500.J17(GND#J17) J500.J20(GND#J20) J500.J23(GND#J23) J500.J26(GND#J26) J500.J29(GND#J29) J500.J32(GND#J32) J500.J35(GND#J35) J500.J38(GND#J38) J500.J40(GND#J40) J500.K02(GND#K02) J500.K03(GND#K03) J500.K06(GND#K06) J500.K09(GND#K09) J500.K12(GND#K12) J500.K15(GND#K15) J500.K18(GND#K18) J500.K21(GND#K21) J500.K24(GND#K24) J500.K27(GND#K27) J500.K30(GND#K30) J500.K33(GND#K33) J500.K36(GND#K36) J500.K39(GND#K39) L5.1 L7.2 R9.1 R13.2 R14.2 R15.2 R17.1 R18.1 R19.2 R21.1 R26.1 R27.1 R28.1 R29.1 R31.1 R44.1 R52.2 R56.1 TP12.1 U1.5(GND) U1.7(PAD) U2.3(GND) U2.6(GND_TAB) U4.3(GND) U5.2(GND) U6.2(S) U7.1(GND#1) U7.7(GND#7) U7.14(GND#14) U7.20(GND#20) U7.41(GND#41) U7.46(GND#46) U7.53(GND#53) U7.55(GND#55) U7.60(GND#60) U8.B4(VSS#B4) U8.B7(VSS#B7) U8.B11(VSS#B11) U8.B14(VSS#B14) U8.B17(VSS#B17) U8.B20(VSS#B20) U8.B22(VSS#B22) U8.B25(VSS#B25) U8.C2(VSS#C2) U8.C9(VSS#C9) U8.C20(VSS#C20) U8.C22(VSS#C22) U8.C24(VSS#C24) U8.D1(VSS#D1) U8.D2(VSS#D2) U8.D5(VSS#D5) U8.D9(VSS#D9) U8.D11(VSS#D11) U8.D14(VSS#D14) U8.D18(VSS#D18) U8.D20(VSS#D20) U8.D21(VSS#D21) U8.E1(VSS#E1) U8.E2(VSS#E2) U8.E7(VSS#E7) U8.E9(VSS#E9) U8.E16(VSS#E16) U8.E17(VSS#E17) U8.E18(VSS#E18) U8.E25(VSS#E25) U8.E26(VSS#E26) U8.F4(VSS#F4) U8.F23(VSS#F23) U8.F24(VSS#F24) U8.H2(VSS#H2) U8.H4(VSS#H4) U8.H25(VSS#H25) U8.H26(VSS#H26) U8.J23(VSS#J23) U8.J24(VSS#J24) U8.K2(VSS#K2) U8.L2(VSS#L2) U8.L3(VSS#L3) U8.L4(VSS#L4) U8.M1(VSS#M1) U8.M2(VSS#M2) U8.M23(VSS#M23) U8.M24(VSS#M24) U8.N2(VSS#N2) U8.N3(VSS#N3) U8.N4(VSS#N4) U8.P2(VSS#P2) U8.R23(VSS#R23) U8.R24(VSS#R24) U8.T2(VSS#T2) U8.T4(VSS#T4) U8.T25(VSS#T25) U8.T26(VSS#T26) U8.V4(VSS#V4) U8.V23(VSS#V23) U8.V24(VSS#V24) U8.W1(VSS#W1) U8.W2(VSS#W2) U8.W7(VSS#W7) U8.W9(VSS#W9) U8.W25(VSS#W25) U8.W26(VSS#W26) U8.X1(VSS#X1) U8.X2(VSS#X2) U8.X5(VSS#X5) U8.X9(VSS#X9) U8.X11(VSS#X11) U8.X14(VSS#X14) U8.X18(VSS#X18) U8.X20(VSS#X20) U8.X21(VSS#X21) U8.Y2(VSS#Y2) U8.Y9(VSS#Y9) U8.Y20(VSS#Y20) U8.Y22(VSS#Y22) U8.Y24(VSS#Y24) U8.Z4(VSS#Z4) U8.Z7(VSS#Z7) U8.Z11(VSS#Z11) U8.Z14(VSS#Z14) U8.Z17(VSS#Z17) U8.Z20(VSS#Z20) U8.Z22(VSS#Z22) U8.Z25(VSS#Z25) U9.8(GND#8) U9.9(GND#9) U9.14(2OEZ) U9.15(1OEZ) U9.17(EP) U10.2(GND) U11.5(GND) U13.5(BIAS) U14.3(GND) U16.2(S) U17.3(GND) U17.6(GND_TAB)
P1V8: C10.2 C43.2 C44.2 C45.2 C46.2 C47.2 C48.2 C49.2 C50.2 C51.2 C52.2 C53.2 C54.2 C55.2 C56.2 C57.2 C58.2 C59.2 C60.2 C61.2 C62.2 C63.2 C64.2 C65.2 C66.2 C67.2 C68.2 C69.2 C70.2 C71.2 C72.2 C73.2 C76.2 TP5.1 U2.4(VOUT) U8.A5(VCC#A5) U8.A6(VCC#A6) U8.A7(VCCI#A7) U8.A8(VCCI#A8) U8.A11(VCCI#A11) U8.A16(VCCI#A16) U8.A17(VCCI#A17) U8.A18(VCCI#A18) U8.A21(VCCI#A21) U8.A22(VCCI#A22) U8.A23(VCCI#A23) U8.AA2(VCC#AA2) U8.AA5(VCC#AA5) U8.AA6(VCC#AA6) U8.AA7(VCCI#AA7) U8.AA8(VCCI#AA8) U8.AA11(VCCI#AA11) U8.AA16(VCCI#AA16) U8.AA17(VCCI#AA17) U8.AA18(VCCI#AA18) U8.AA21(VCCI#AA21) U8.AA22(VCCI#AA22) U8.AA23(VCCI#AA23) U8.B2(VCC#B2) U8.C1(VCC#C1) U8.D10(VCC#D10) U8.D12(VCC#D12) U8.D19(VCC#D19) U8.D22(VCC#D22) U8.E8(VCC#E8) U8.E19(VCC#E19) U8.E20(VCC#E20) U8.E21(VCC#E21) U8.E22(VCC#E22) U8.F1(VCC#F1) U8.F2(VCC#F2) U8.J2(VCC#J2) U8.K1(VCC#K1) U8.L1(VCC#L1) U8.L25(VCC#L25) U8.M3(VCC#M3) U8.M4(VCC#M4) U8.M25(VCC#M25) U8.N1(VCC#N1) U8.N25(VCC#N25) U8.P1(VCC#P1) U8.R2(VCC#R2) U8.V1(VCC#V1) U8.V2(VCC#V2) U8.W8(VCC#W8) U8.W19(VCC#W19) U8.W20(VCC#W20) U8.W21(VCC#W21) U8.W22(VCC#W22) U8.X10(VCC#X10) U8.X12(VCC#X12) U8.X19(VCC#X19) U8.X22(VCC#X22) U8.Y1(VCC#Y1) U8.Z1(VCC#Z1) U8.Z2(VCC#Z2) U9.16(VCCB) U10.6(VCCB)
P3V3: C1.2 C4.2 C5.2 C8.2 C12.2 C74.2 C75.2 C77.2 J3.3 L1.1 L2.1 L3.1 L4.1 R1.1 R2.1 R3.1 R4.1 R5.1 R6.2 R7.1 R11.1 R32.1 R33.1 R42.2 U2.2(VIN) U3.3(D) U4.5(PWR) U9.1(VCCA) U9.2(1DIR) U9.3(2DIR) U10.1(VCCA) U11.1(VCC) U14.5(PWR)
P12V: C9.2 C17.2 C18.2 C86.1 C87.1 C88.2 C93.2 J500.C35(12P0V#C35) J500.C37(12P0V#C37) R50.2 R53.1 U1.6(IN) U5.4(/MR) U5.5(VCC) U7.11(12V#11) U7.48(12V#48) U7.50(12V#50) U13.13(VIN#13) U13.14(VIN#14) U15.2(S) U17.1(VIN)
VCC2: C11.2 C31.2 C32.2 C33.2 C34.2 C35.2 C36.2 C37.2 C38.2 C39.2 C40.2 C41.2 C42.2 C94.2 R8.2 R10.1 R55.2 TP4.1 U1.1(OUT) U8.A3(VCC2#A3) U8.A4(VCC2#A4) U8.A25(VCC2#A25) U8.AA3(VCC2#AA3) U8.AA4(VCC2#AA4) U8.AA25(VCC2#AA25) U8.B26(VCC2#B26) U8.L26(VCC2#L26) U8.M26(VCC2#M26) U8.N26(VCC2#N26) U8.Z26(VCC2#Z26) U17.2(VOUT)
VCC2_EN: R11.2 TP6.1 U1.4(EN) U2.5(ERROR) U4.4(Y) U17.5(EN)
3P3VAUX: J500.D32(3P3VAUX)
DAD_ADDR_0: J500.A14(DP4_M2C_P) U7.19(A0)
DAD_ADDR_1: J500.A18(DP5_M2C_P) U7.18(A1)
DAD_ADDR_2: J500.A22(DP1_C2M_P) U7.17(A2)
DAD_ADDR_3: J500.A26(DP2_C2M_P) U7.16(A3)
DAD_IRQZ: J500.B08(DP8_M2C_P) R1.2 U7.43(IRQZ)
DAD_MODE_0: J500.A06(DP2_M2C_P) U7.3(MODE0)
DAD_MODE_1: J500.A10(DP3_M2C_P) U7.2(MODE1)
DAD_OEZ: J500.B04(DP9_M2C_P) R2.2 U7.6(OEZ)
DAD_SEL_0: J500.A30(DP3_C2M_P) U7.5(SEL0)
DAD_SEL_1: J500.A34(DP4_C2M_P) U7.4(SEL1)
DAD_STRB: J500.A38(DP5_C2M_P) U7.15(STROBE)
DMD_RSTZ: J500.A02(DP1_M2C_P) R26.2 U7.59(RESETZ) U9.4(1A1)
DMD_RSTZ_1V8: R22.1 U8.G4(PWRDNZ)
DMD_TEMP_N: C78.1 R35.1 U8.W16(TEMP_N)
DMD_TEMP_P: C78.2 R34.1 U8.W17(TEMP_P)
I2C_SCL_3P3V: J3.1 R32.2 U11.8(SCL)
I2C_SDA_3P3V: J3.2 R33.2 U11.7(SDA)
M_DCLKA_N: J500.K05(CLK2_M2C_N) U8.H23(DCLK_CN)
M_DCLKA_P: J500.K04(CLK2_M2C_P) U8.G23(DCLK_CP)
M_DCLKB_N: J500.J03(CLK3_M2C_N) U8.T23(DCLK_DN)
M_DCLKB_P: J500.J02(CLK3_M2C_P) U8.U23(DCLK_DP)
M_DDA00_N: J500.D21(LA17_N_CC) U8.B18(D_CN<0>)
M_DDA00_P: J500.D20(LA17_P_CC) U8.B19(D_CP<0>)
M_DDA01_N: J500.C23(LA18_N_CC) U8.H24(D_CN<1>)
M_DDA01_P: J500.C22(LA18_P_CC) U8.G24(D_CP<1>)
M_DDA02_N: J500.H23(LA19_N) U8.L23(D_CN<2>)
M_DDA02_P: J500.H22(LA19_P) U8.K23(D_CP<2>)
M_DDA03_N: J500.G22(LA20_N) U8.C18(D_CN<3>)
M_DDA03_P: J500.G21(LA20_P) U8.C19(D_CP<3>)
M_DDA04_N: J500.H26(LA21_N) U8.A19(D_CN<4>)
M_DDA04_P: J500.H25(LA21_P) U8.A20(D_CP<4>)
M_DDA05_N: J500.G25(LA22_N) U8.E24(D_CN<5>)
M_DDA05_P: J500.G24(LA22_P) U8.D24(D_CP<5>)
M_DDA06_N: J500.D24(LA23_N) U8.K25(D_CN<6>)
M_DDA06_P: J500.D23(LA23_P) U8.J25(D_CP<6>)
M_DDA07_N: J500.H29(LA24_N) U8.C26(D_CN<7>)
M_DDA07_P: J500.H28(LA24_P) U8.D26(D_CP<7>)
M_DDA08_N: J500.G28(LA25_N) U8.C21(D_CN<8>)
M_DDA08_P: J500.G27(LA25_P) U8.B21(D_CP<8>)
M_DDA09_N: J500.D27(LA26_N) U8.G25(D_CN<9>)
M_DDA09_P: J500.D26(LA26_P) U8.F25(D_CP<9>)
M_DDA10_N: J500.C27(LA27_N) U8.A24(D_CN<10>)
M_DDA10_P: J500.C26(LA27_P) U8.B24(D_CP<10>)
M_DDA11_N: J500.H32(LA28_N) U8.J26(D_CN<11>)
M_DDA11_P: J500.H31(LA28_P) U8.K26(D_CP<11>)
M_DDA12_N: J500.G31(LA29_N) U8.D25(D_CN<12>)
M_DDA12_P: J500.G30(LA29_P) U8.C25(D_CP<12>)
M_DDA13_N: J500.H35(LA30_N) U8.E23(D_CN<13>)
M_DDA13_P: J500.H34(LA30_P) U8.D23(D_CP<13>)
M_DDA14_N: J500.G34(LA31_N) U8.B23(D_CN<14>)
M_DDA14_P: J500.G33(LA31_P) U8.C23(D_CP<14>)
M_DDA15_N: J500.H38(LA32_N) U8.K24(D_CN<15>)
M_DDA15_P: J500.H37(LA32_P) U8.L24(D_CP<15>)
M_DDB00_N: J500.K26(HB00_CC_N) U8.Z18(D_DN<0>)
M_DDB00_P: J500.K25(HB00_CC_P) U8.Z19(D_DP<0>)
M_DDB01_N: J500.J25(HB01_N) U8.T24(D_DN<1>)
M_DDB01_P: J500.J24(HB01_P) U8.U24(D_DP<1>)
M_DDB02_N: J500.F23(HB02_N) U8.N23(D_DN<2>)
M_DDB02_P: J500.F22(HB02_P) U8.P23(D_DP<2>)
M_DDB03_N: J500.E22(HB03_N) U8.Y18(D_DN<3>)
M_DDB03_P: J500.E21(HB03_P) U8.Y19(D_DP<3>)
M_DDB04_N: J500.F26(HB04_N) U8.AA19(D_DN<4>)
M_DDB04_P: J500.F25(HB04_P) U8.AA20(D_DP<4>)
M_DDB05_N: J500.E25(HB05_N) U8.W24(D_DN<5>)
M_DDB05_P: J500.E24(HB05_P) U8.X24(D_DP<5>)
M_DDB06_N: J500.K29(HB06_N_CC) U8.P25(D_DN<6>)
M_DDB06_P: J500.K28(HB06_P_CC) U8.R25(D_DP<6>)
M_DDB07_N: J500.J28(HB07_N) U8.Y26(D_DN<7>)
M_DDB07_P: J500.J27(HB07_P) U8.X26(D_DP<7>)
M_DDB08_N: J500.F29(HB08_N) U8.Y21(D_DN<8>)
M_DDB08_P: J500.F28(HB08_P) U8.Z21(D_DP<8>)
M_DDB09_N: J500.E28(HB09_N) U8.U25(D_DN<9>)
M_DDB09_P: J500.E27(HB09_P) U8.V25(D_DP<9>)
M_DDB10_N: J500.K32(HB10_N) U8.AA24(D_DN<10>)
M_DDB10_P: J500.K31(HB10_P) U8.Z24(D_DP<10>)
M_DDB11_N: J500.J31(HB11_N) U8.R26(D_DN<11>)
M_DDB11_P: J500.J30(HB11_P) U8.P26(D_DP<11>)
M_DDB12_N: J500.F32(HB12_N) U8.X25(D_DN<12>)
M_DDB12_P: J500.F31(HB12_P) U8.Y25(D_DP<12>)
M_DDB13_N: J500.E31(HB13_N) U8.W23(D_DN<13>)
M_DDB13_P: J500.E30(HB13_P) U8.X23(D_DP<13>)
M_DDB14_N: J500.K35(HB14_N) U8.Z23(D_DN<14>)
M_DDB14_P: J500.K34(HB14_P) U8.Y23(D_DP<14>)
M_DDB15_N: J500.J34(HB15_N) U8.P24(D_DN<15>)
M_DDB15_P: J500.J33(HB15_P) U8.N24(D_DP<15>)
M_SCTRLA_N: J500.G37(LA33_N) U8.F26(SCTRL_CN)
M_SCTRLA_P: J500.G36(LA33_P) U8.G26(SCTRL_CP)
M_SCTRLB_N: J500.F35(HB16_N) U8.V26(SCTRL_DN)
M_SCTRLB_P: J500.F34(HB16_P) U8.U26(SCTRL_DP)
MBRST0: TP23.1 U7.22(OUT0) U8.E14(MBRST<0>)
MBRST1: TP22.1 U7.24(OUT1) U8.D13(MBRST<1>)
MBRST2: TP21.1 U7.27(OUT2) U8.E13(MBRST<2>)
MBRST3: TP20.1 U7.29(OUT3) U8.C12(MBRST<3>)
MBRST4: TP19.1 U7.32(OUT4) U8.E12(MBRST<4>)
MBRST5: TP18.1 U7.34(OUT5) U8.C11(MBRST<5>)
MBRST6: TP17.1 U7.37(OUT6) U8.D16(MBRST<6>)
MBRST7: TP16.1 U7.39(OUT7) U8.C15(MBRST<7>)
MBRST8: TP15.1 U7.62(OUT8) U8.W14(MBRST<8>)
MBRST9: TP14.1 U7.64(OUT9) U8.X13(MBRST<9>)
MBRST10: TP13.1 U7.67(OUT10) U8.W13(MBRST<10>)
MBRST11: TP11.1 U7.69(OUT11) U8.Y12(MBRST<11>)
MBRST12: TP10.1 U7.72(OUT12) U8.W12(MBRST<12>)
MBRST13: TP9.1 U7.74(OUT13) U8.Y11(MBRST<13>)
MBRST14: TP8.1 U7.77(OUT14) U8.Y15(MBRST<14>)
MBRST15: TP7.1 U7.79(OUT15) U8.X16(MBRST<15>)
MODEB: J500.B12(DP7_M2C_P) TP1.1
P3P3V1: C2.2 J500.C39(3P3V#C39) L1.2
P3P3V2: C6.2 J500.D36(3P3V#D36) L3.2
P3P3V3: C3.2 J500.D38(3P3V#D38) L2.2
P3P3V4: C7.2 J500.D40(3P3V#D40) L4.2
RES0: J500.B40(RES0)
RES1: J500.B01(RES1)
S_DCLKA_N: J500.H05(CLK0_M2C_N) U8.B3(DCLK_AN)
S_DCLKA_P: J500.H04(CLK0_M2C_P) U8.C3(DCLK_AP)
S_DCLKB_N: J500.G03(CLK1_M2C_N) U8.Y4(DCLK_BN)
S_DCLKB_P: J500.G02(CLK1_M2C_P) U8.Y5(DCLK_BP)
S_DDA00_N: J500.G07(LA00_N_CC) U8.E10(D_AN<0>)
S_DDA00_P: J500.G06(LA00_P_CC) U8.E11(D_AP<0>)
S_DDA01_N: J500.D09(LA01_N_CC) U8.D6(D_AN<1>)
S_DDA01_P: J500.D08(LA01_P_CC) U8.C6(D_AP<1>)
S_DDA02_N: J500.H08(LA02_N) U8.E3(D_AN<2>)
S_DDA02_P: J500.H07(LA02_P) U8.D3(D_AP<2>)
S_DDA03_N: J500.G10(LA03_N) U8.C7(D_AN<3>)
S_DDA03_P: J500.G09(LA03_P) U8.C8(D_AP<3>)
S_DDA04_N: J500.H11(LA04_N) U8.D8(D_AN<4>)
S_DDA04_P: J500.H10(LA04_P) U8.D7(D_AP<4>)
S_DDA05_N: J500.D12(LA05_N) U8.E6(D_AN<5>)
S_DDA05_P: J500.D11(LA05_P) U8.E5(D_AP<5>)
S_DDA06_N: J500.C11(LA06_N) U8.C5(D_AN<6>)
S_DDA06_P: J500.C10(LA06_P) U8.C4(D_AP<6>)
S_DDA07_N: J500.H14(LA07_N) U8.B8(D_AN<7>)
S_DDA07_P: J500.H13(LA07_P) U8.B9(D_AP<7>)
S_DDA08_N: J500.G13(LA08_N) U8.B6(D_AN<8>)
S_DDA08_P: J500.G12(LA08_P) U8.B5(D_AP<8>)
S_DDA09_N: J500.D15(LA09_N) U8.C10(D_AN<9>)
S_DDA09_P: J500.D14(LA09_P) U8.B10(D_AP<9>)
S_DDA10_N: J500.C15(LA10_N) U8.A9(D_AN<10>)
S_DDA10_P: J500.C14(LA10_P) U8.A10(D_AP<10>)
S_DDA11_N: J500.H17(LA11_N) U8.C13(D_AN<11>)
S_DDA11_P: J500.H16(LA11_P) U8.C14(D_AP<11>)
S_DDA12_N: J500.G16(LA12_N) U8.B12(D_AN<12>)
S_DDA12_P: J500.G15(LA12_P) U8.B13(D_AP<12>)
S_DDA13_N: J500.D18(LA13_N) U8.C17(D_AN<13>)
S_DDA13_P: J500.D17(LA13_P) U8.C16(D_AP<13>)
S_DDA14_N: J500.C19(LA14_N) U8.B15(D_AN<14>)
S_DDA14_P: J500.C18(LA14_P) U8.B16(D_AP<14>)
S_DDA15_N: J500.H20(LA15_N) U8.D15(D_AN<15>)
S_DDA15_P: J500.H19(LA15_P) U8.E15(D_AP<15>)
S_DDB00_N: J500.F05(HA00_N_CC) U8.W10(D_BN<0>)
S_DDB00_P: J500.F04(HA00_P_CC) U8.W11(D_BP<0>)
S_DDB01_N: J500.E03(HA01_N_CC) U8.Z3(D_BN<1>)
S_DDB01_P: J500.E02(HA01_P_CC) U8.Y3(D_BP<1>)
S_DDB02_N: J500.K08(HA02_N) U8.W4(D_BN<2>)
S_DDB02_P: J500.K07(HA02_P) U8.X4(D_BP<2>)
S_DDB03_N: J500.J07(HA03_N) U8.Y7(D_BN<3>)
S_DDB03_P: J500.J06(HA03_P) U8.Y8(D_BP<3>)
S_DDB04_N: J500.F08(HA04_N) U8.X8(D_BN<4>)
S_DDB04_P: J500.F07(HA04_P) U8.X7(D_BP<4>)
S_DDB05_N: J500.E07(HA05_N) U8.Y6(D_BN<5>)
S_DDB05_P: J500.E06(HA05_P) U8.X6(D_BP<5>)
S_DDB06_N: J500.K11(HA06_N) U8.X3(D_BN<6>)
S_DDB06_P: J500.K10(HA06_P) U8.W3(D_BP<6>)
S_DDB07_N: J500.J10(HA07_N) U8.Z8(D_BN<7>)
S_DDB07_P: J500.J09(HA07_P) U8.Z9(D_BP<7>)
S_DDB08_N: J500.F11(HA08_N) U8.Z6(D_BN<8>)
S_DDB08_P: J500.F10(HA08_P) U8.Z5(D_BP<8>)
S_DDB09_N: J500.E10(HA09_N) U8.Y10(D_BN<9>)
S_DDB09_P: J500.E09(HA09_P) U8.Z10(D_BP<9>)
S_DDB10_N: J500.K14(HA10_N) U8.AA9(D_BN<10>)
S_DDB10_P: J500.K13(HA10_P) U8.AA10(D_BP<10>)
S_DDB11_N: J500.J13(HA11_N) U8.Y13(D_BN<11>)
S_DDB11_P: J500.J12(HA11_P) U8.Y14(D_BP<11>)
S_DDB12_N: J500.F14(HA12_N) U8.Z12(D_BN<12>)
S_DDB12_P: J500.F13(HA12_P) U8.Z13(D_BP<12>)
S_DDB13_N: J500.E13(HA13_N) U8.Y17(D_BN<13>)
S_DDB13_P: J500.E12(HA13_P) U8.Y16(D_BP<13>)
S_DDB14_N: J500.J16(HA14_N) U8.Z15(D_BN<14>)
S_DDB14_P: J500.J15(HA14_P) U8.Z16(D_BP<14>)
S_DDB15_N: J500.F17(HA15_N) U8.X15(D_BN<15>)
S_DDB15_P: J500.F16(HA15_P) U8.W15(D_BP<15>)
S_SCTRLA_N: J500.G19(LA16_N) U8.E4(SCTRL_AN)
S_SCTRLA_P: J500.G18(LA16_P) U8.D4(SCTRL_AP)
S_SCTRLB_N: J500.E16(HA16_N) U8.W5(SCTRL_BN)
S_SCTRLB_P: J500.E15(HA16_P) U8.W6(SCTRL_BP)
SCP_CLK: J500.B32(DP7_C2M_P) R27.2 U7.56(SCPCK) U9.5(1A2)
SCP_CLK_1V8: R23.1 U8.U2(SCPCLK)
SCP_DAD_CSZ: J500.B24(DP9_C2M_P) R3.2 U7.58(SCPENZ)
SCP_DMD_CSZ: J500.C06(DP0_M2C_P) R4.2 R29.2 U9.7(2A2) U10.5(DIR)
SCP_DMD_CSZ_1V8: R25.1 U8.U4(SCPENZ)
SCP_MISO: J500.B36(DP6_C2M_P) R5.2 R16.2 R30.2
SCP_MISO_1V8: R31.2 U8.U3(SCPDO) U10.4(B)
SCP_MOSI: J500.C02(DP0_C2M_P) R28.2 U7.57(SCPDI) U9.6(2A1)
SCP_MOSI_1V8: R24.1 U8.T3(SCPDI)
V_OFFSET: C13.2 C14.2 C15.2 C16.2 D1.2(CATHODE) R12.2 R51.2 R54.1 TP24.1 U7.23(VOFFSET_RAIL#23) U7.28(VOFFSET_RAIL#28) U7.33(VOFFSET_RAIL#33) U7.38(VOFFSET_RAIL#38) U7.49(VOFFSET) U7.63(VOFFSET_RAIL#63) U7.68(VOFFSET_RAIL#68) U7.73(VOFFSET_RAIL#73) U7.78(VOFFSET_RAIL#78)
VADJ: J500.E39(VADJ#E39) J500.F40(VADJ#F40) J500.G39(VADJ#G39) J500.H40(VADJ#H40)
VBIAS: C25.2 C26.2 C27.2 C28.2 D3.C R49.2 TP26.1 U7.9(VBIAS) U7.21(VBAIS_RAIL) U7.30(VBIAS_RAIL#30) U7.31(VBIAS_RAIL#31) U7.40(VBIAS_RAIL#40) U7.61(VBIAS_RAIL#61) U7.70(VBIAS_RAIL#70) U7.71(VBIAS_RAIL#71) U7.80(VBIAS_RAIL#80)
VIO_B_M2C: J500.J39(VIO_B_M2C#J39) J500.K40(VIO_B_M2C#K40)
VR_PG: D5.C R43.2 TP40.1
VR_PG_NEG: R42.1 R43.1 U13.8(PGOOD)
VREF_A_M2C: J500.H01(VREF_A_M2C)
VREF_B_M2C: J500.K01(VREF_B_M2C)
VRESET_DAD: C21.2 C22.2 C23.2 C24.2 D2.A R41.1 TP27.1 U7.13(VRESET)
VRESET_EN: D7.2(CATHODE) R48.1 R52.1 R53.2 R54.2 U13.12(EN) U15.3(D)
VRESET_EXT: C80.1 C81.1 C82.1 C83.1 C84.1 C85.1 C88.1 C90.1 C91.1 C92.1 D6.A D7.1(ANODE) R20.1 R45.1 R46.1 R47.1 R48.2 TP41.1 U13.10(AGND) U13.15(PGND#15) U13.16(PGND#16) U13.17(PAD)
VRESET_RAIL: R20.2 R41.2 TP25.1 U7.25(VRESET_RAIL#25) U7.26(VRESET_RAIL#26) U7.35(VRESET_RAIL#35) U7.36(VRESET_RAIL#36) U7.65(VRESET_RAIL#65) U7.66(VRESET_RAIL#66) U7.75(VRESET_RAIL#75) U7.76(VRESET_RAIL#76) U7.81(PAD)
N16506021: R21.2 TP30.1 U8.W18(PROG_FUSE_EN)
N16506047: TP33.1 U8.G3(SCP_TEST_MUX)
N16506207: TP32.1 U8.D17(BIST_D)
N16506209: TP31.1 U8.X17(BIST_C)
N16506211: TP29.1 U8.K4(BIST_B)
N16506213: TP28.1 U8.P4(BIST_A)
N16506277: TP34.1 U8.H3(TP0)
N16506279: TP35.1 U8.G2(TP1)
N16506281: TP36.1 U8.F3(TP2)
N16551414: D3.A L6.1 U7.8(VBIAS_SWL)
N16555452: C29.2 C30.2 L6.2 U7.10(VBIAS_LHI)
N16558116: D2.C L5.2 U7.12(VRESET_SWL)
N16559232: C19.2 C20.2 U7.47(V5REG)
N16562882: R17.2 U7.45(DEV_ID1)
N16562886: R18.2 U7.44(DEV_ID0)
N16780951: R6.1 TP3.1 U2.1(EN)
N16783652: R16.1 U7.42(SCPDO)
N16819402: R19.1 U7.54(NC_54)
N16824071: R8.1 R9.2 U1.2(FB)
N16824656: R7.2 TP2.1 U1.3(PG)
N16836860: R12.1 R13.1 U3.1(G)
N16836862: R14.1 U3.2(S) U4.2(A)
N16841509: R10.2 U6.3(D)
N16842070: R15.1 U5.1(/RESET) U14.2(A)
N16883881: R34.2 U11.2(D+)
N16883883: TP37.1 U11.6(ALERT)
